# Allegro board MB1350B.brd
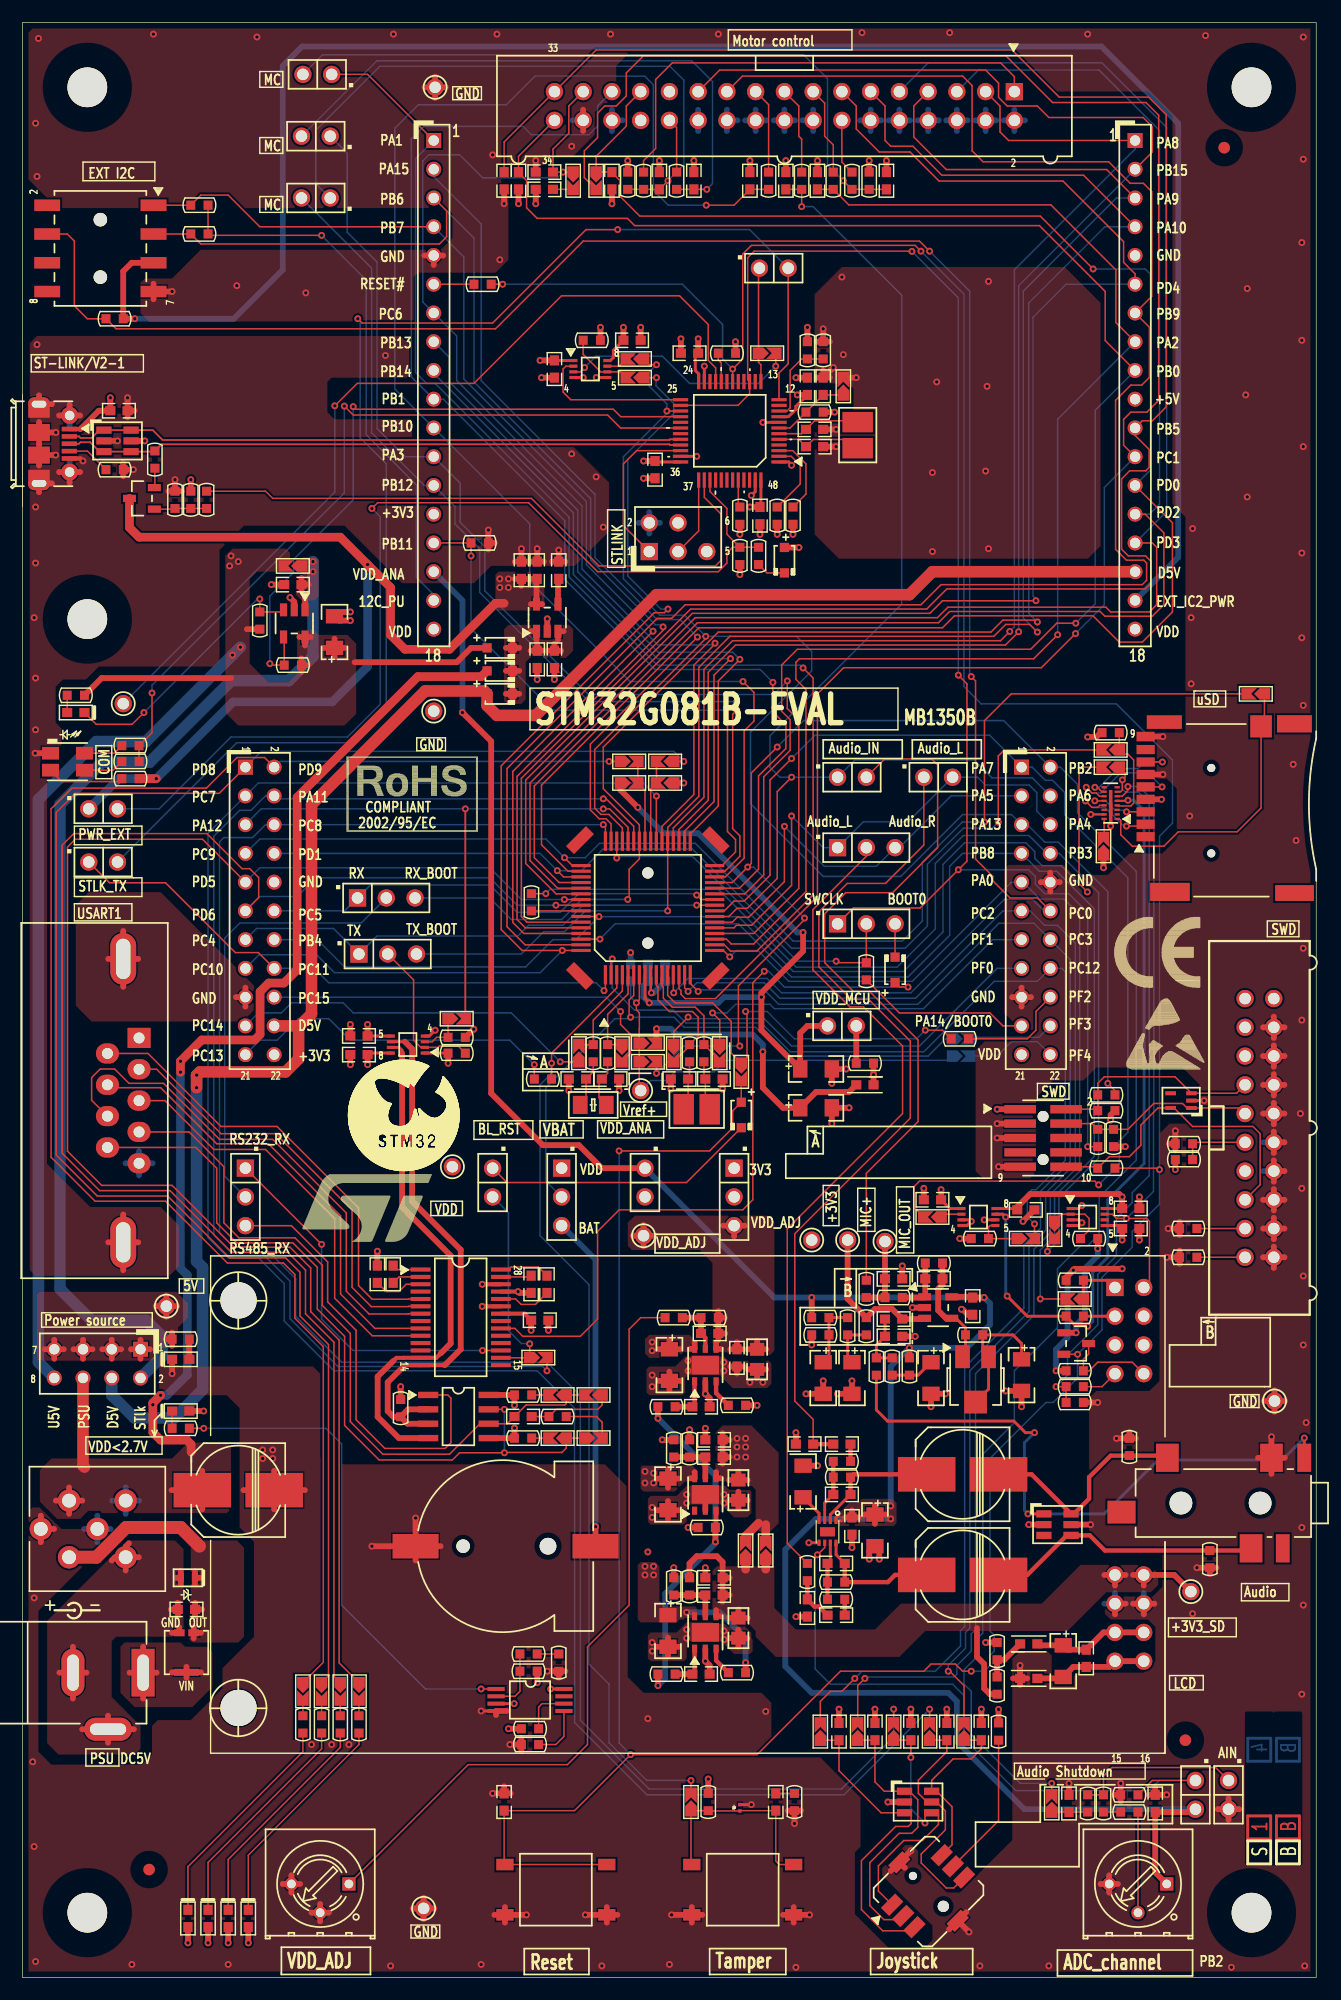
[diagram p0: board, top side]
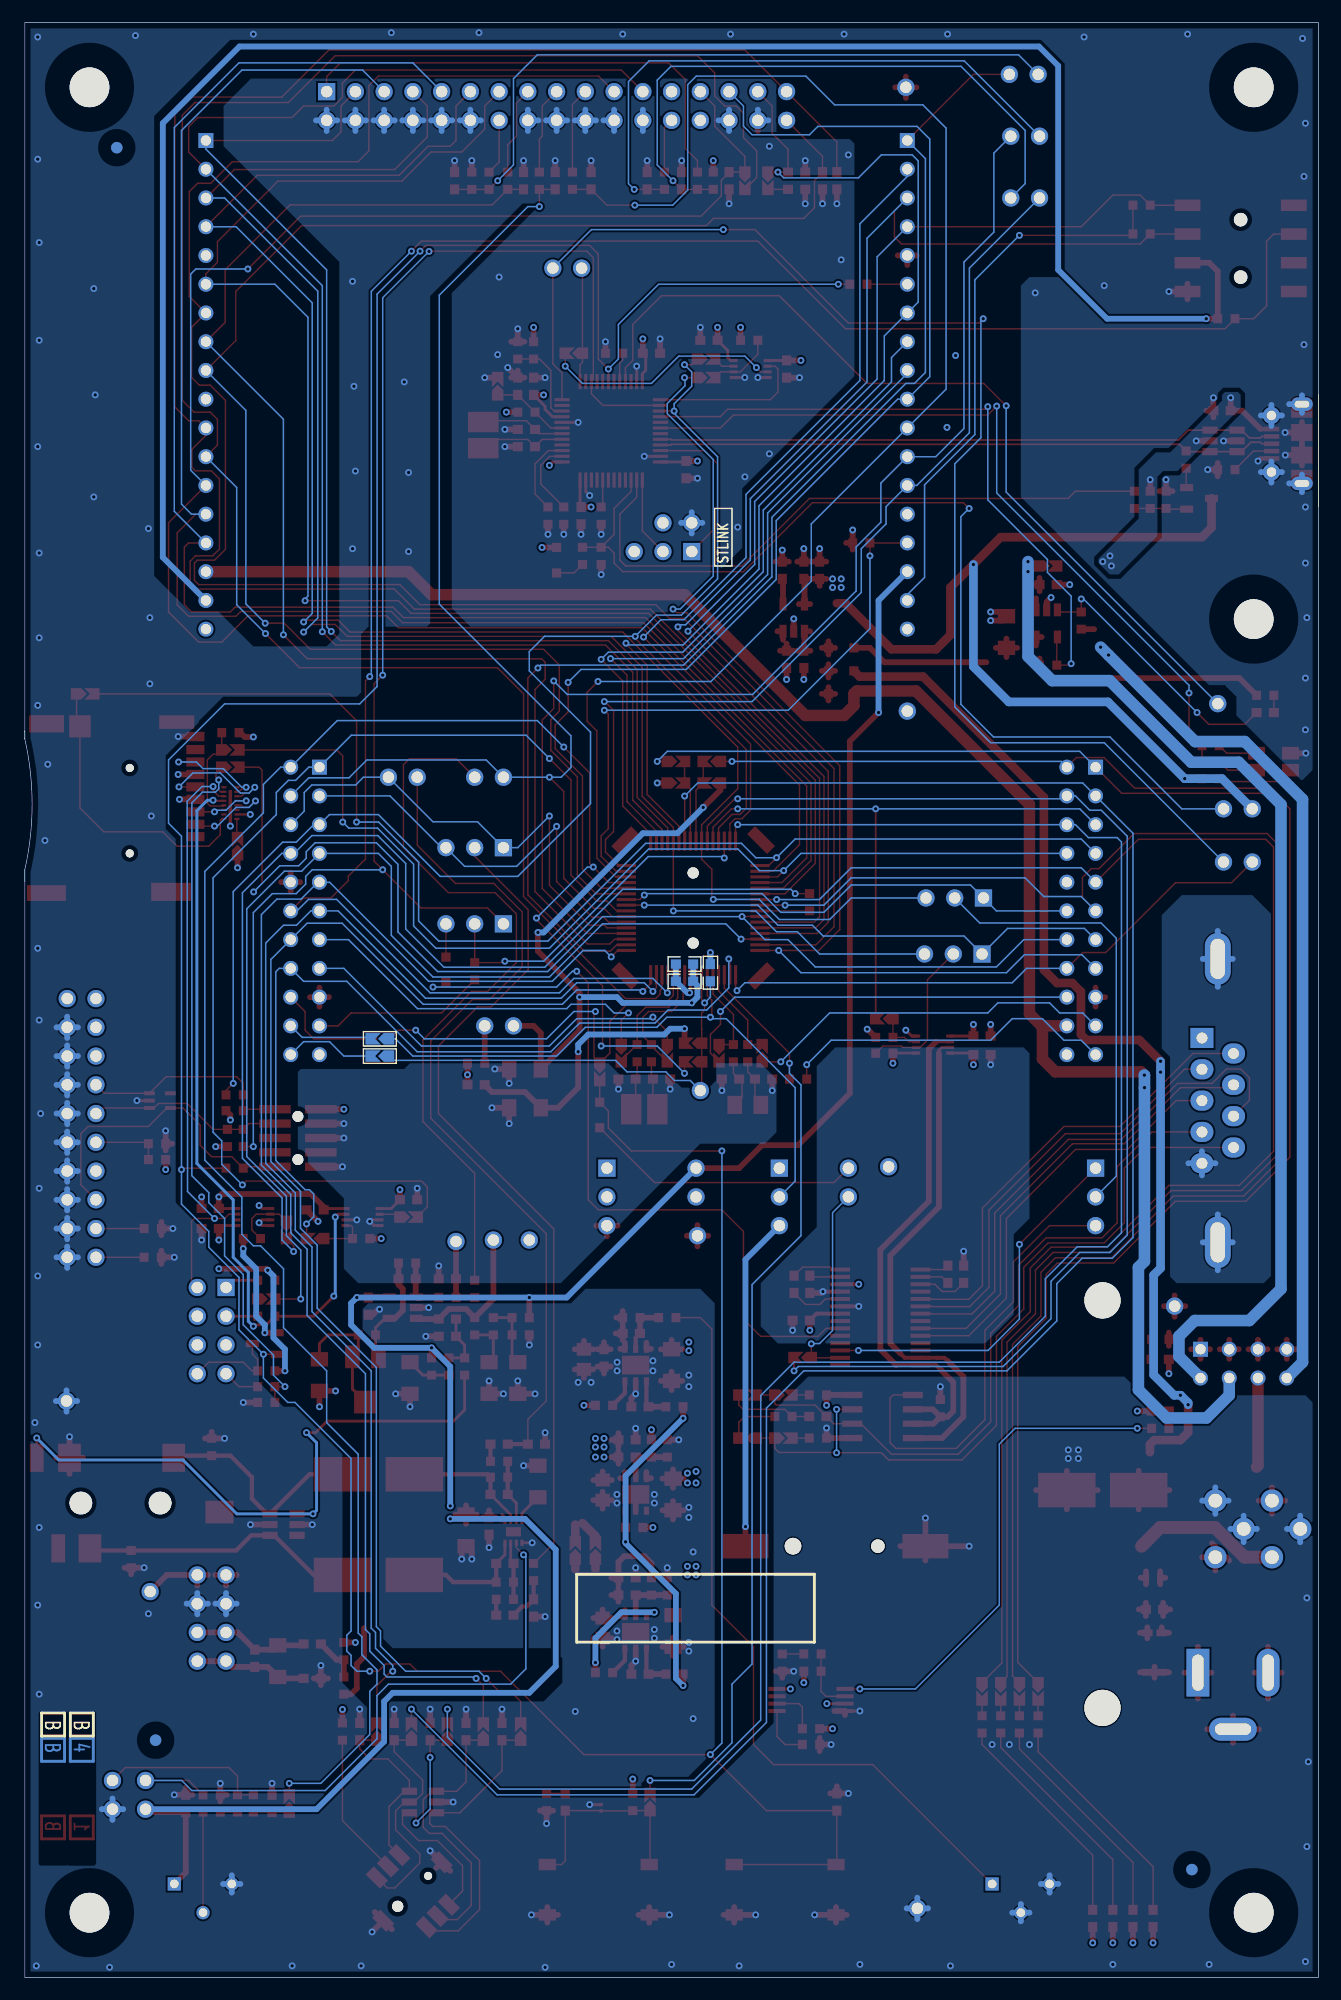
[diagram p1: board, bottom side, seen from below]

Outline 114.3 x 172.72 mm; copper layers: TOP, L2_VCC, L3_GND, BOTTOM. Coordinates in mm from the lower left corner of the outline.
Outline path: 114.3,110.11 114.3,172.72 0,172.72 0,0 114.3,0 114.3,96.86 ; 114.3,110.11 114.3,109.43 ; 114.3,110.11 114.3,109.43 ; 114.3,109.43 arc(113.66,103.65) 114.3,97.87 ; 114.3,97.87 114.3,96.86 ; 114.3,97.87 114.3,96.86

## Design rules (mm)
net group STL_USB_D: nets STL_USB_DM STL_USB_DP

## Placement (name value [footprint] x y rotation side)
B1  TD-0341 [RESET_Black]  [PB10]  47.12 7.75 0 top
B2  Tamper  [PB10]  63.63 7.75 0 top
B3  -  [MT-008A]  80.01 7.62 315 top
BT1  CR1220 holder  [BAT_2SM_CR1220]  42.67 38.1 180 top
C1  [N_A]  [0603C]  46.1 159.51 0 top
C2  [N_A]  [0603C]  42.55 158.75 90 top
C3  [N_A]  [0603C]  43.81 158.75 90 top
C4  [N_A]  [0603C]  52.07 158.75 90 top
C5  1nF  [0603C]  56.26 158.75 270 top
C6  100nF  [0603C]  59.31 158.75 270 top
C7  [N_A]  [0603C]  64.26 158.75 270 top
C8  [N_A]  [0603C]  67.44 158.75 270 top
C9  [N_A]  [0603C]  70.23 158.75 270 top
C10  100nF  [0603C]  76.33 158.75 270 top
C11  10nF  [0603C]  46.1 157.99 0 top
C12  100nF  [0603C]  53.85 144.65 180 top
C13  100nF  [0603C]  58.93 143.51 0 top
C14  100nF  [0603C]  46.99 142.11 90 top
C15  100nF  [0603C]  69.34 140.59 270 top
C16  100nF  [0603C]  70.74 140.59 270 top
C17  100nF  [0603C]  8.51 138.43 180 top
C18  10pF  [0603C]  69.98 136.78 0 top
C19  10pF  [0603C]  69.98 135.25 0 top
C20  100nF  [0603C]  55.88 133.22 90 top
C21  100nF  [0603C]  65.15 129.16 90 top
C22  100nF  [0603C]  44.07 124.33 270 top
C23  1uF_X5R_0603  [0603C]  45.47 124.33 90 top
C24  10nF_X7R_0603  [0603C]  47.37 124.33 270 top
C25  100nF  [0603C]  23.88 123.06 0 top
C26  1uF_X5R_0603  [0603C]  45.47 116.46 90 top
C27  100nF  [0603C]  46.99 116.46 90 top
C28  4.7uF  [TAN-A]  27.56 118.87 270 top
C29  100nF  [0603C]  29.72 83.19 0 top
C30  100nF  [0603C]  29.72 81.53 0 top
C31  4.7uF  [TAN-A]  70.1 80.26 180 top
C32  100nF  [0603C]  56.01 89.53 180 bottom
C33  100nF  [0603C]  56.01 88.01 0 bottom
C34  3.9pF  [0603C]  49.02 79.38 180 top
C35  3.9pF  [0603C]  51.94 79.38 0 top
C36  3.9pF  [0603C]  58.04 79.38 180 top
C37  3.9pF  [0603C]  61.09 79.38 0 top
C38  10nF  [0603C]  53.72 88.77 270 bottom
C39  1uF  [TAN-A]  70.1 76.83 180 top
C40  100nF  [0603C]  80.39 68.71 0 top
C41  100nF  [0603C]  97.92 67.94 180 top
C42  100nF  [0603C]  88.65 67.82 180 top
C43  100nF  [0603C]  97.92 66.17 180 top
C44  100nF  [0603C]  31.34 62.13 90 top
C45  100nF  [0603C]  32.74 62.13 270 top
C46  [N_A]  [0603C]  76.96 61.72 0 top
C47  180pF  [0603C]  80.52 61.72 180 top
C48  100nF  [0603C]  44.93 61.24 270 top
C49  100nF  [0603C]  46.33 61.24 90 top
C50  100nF  [0603C]  83.95 59.31 90 top
C51  100nF  [0603C]  76.96 58.17 0 top
C52  100nF  [0603C]  45.69 58.06 180 top
C53  [N_A]  [0603C]  60.71 56.9 0 top
C54  47pF  [0603C]  76.96 56.64 0 top
C55  100nF  [0603C]  63.12 54.74 270 top
C56  10uF[ESR<0.2ohm]  [0805C]  64.9 54.61 270 top
C57  4.7uF  [TAN-A]  57.15 54.1 90 top
C58  4.7uF  [TAN-A]  88.27 53.21 90 top
C59  4.7uF  [TAN-A]  70.74 52.96 90 top
C60  2.2uF  [TAN-A]  73.28 52.96 90 top
C61  10uF  [TAN-A]  80.26 52.96 90 top
C62  [N_A]  [0603C]  59.94 50.42 0 top
C63  100nF  [0603C]  44.22 49.56 180 top
C64  100nF  [0603C]  61.09 47.5 180 top
C65  [N_A]  [0603C]  69.09 47.12 0 top
C66  330nF  [0603C]  72.39 47.12 0 top
C67  [N_A]  [0603C]  61.09 45.97 0 top
C68  220uF  [C310M-6]  83.06 44.45 180 top
C69  1uF  [TAN-A]  68.96 43.81 270 top
C70  220uF  [C310M-6]  19.05 43.05 180 top
C71  10uF[ESR<0.2ohm]  [0805C]  63.25 43.05 270 top
C72  4.7uF  [TAN-A]  57.02 42.67 90 top
C73  1.5nF  [0603C]  72.39 42.67 0 top
C74  100nF  [0603C]  73.28 39.88 90 top
C75  1uF  [TAN-A]  75.31 39.5 90 top
C76  1.5nF  [0603C]  71.88 36.58 0 top
C77  220uF  [C310M-6]  83.06 35.56 180 top
C78  [N_A]  [0603C]  69.34 32.64 90 top
C79  100nF  [0603C]  14.48 32.51 180 top
C80  330nF  [0603C]  71.88 32 0 top
C81  100nF  [0603C]  93.98 28.19 270 top
C82  10uF  [TAN-A]  91.95 27.94 90 top
C83  100nF  [0603C]  72.14 21.72 270 top
C84  100nF  [0603C]  75.31 21.72 270 top
C85  100nF  [0603C]  78.49 21.72 270 top
C86  100nF  [0603C]  81.66 21.72 270 top
C87  100nF  [0603C]  84.71 21.72 270 top
C88  100nF  [0603C]  42.55 15.49 270 top
C89  100nF  [0603C]  66.55 15.49 270 top
C90  [N_A]  [0603C]  92.46 15.37 270 top
C91  100nF  [0603C]  100.08 15.37 270 top
C92  4.7uF  [TAN-A]  57.02 30.61 90 top
C93  [N_A]  [0603C]  59.94 26.8 0 top
C94  [N_A]  [0603C]  61.09 33.78 0 top
C95  10uF[ESR<0.2ohm]  [0805C]  63.25 30.86 270 top
C96  100nF  [0603C]  61.09 35.31 180 top
CN1  MC_connector  [IDC34S]  87.63 166.62 270 top
CN2  F206A-2_04MGF-A  [SSM-104-L-DH]  6.87 152.77 90 top
CN3  [N_A]  [SIP2]  65.1 151.03 0 top
CN4  Header 18X1  [HDR_1X18_2R54]  36.32 162.31 270 top
CN5  Header 18X1  [HDR_1X18_2R54]  98.3 162.31 270 top
CN6  1050170001  [MICRO_USB_B_105017]  4.05 135.51 270 top
CN7  [N_A]  [HDR_2X3-1_2R54-6]  55.37 125.98 0 top
CN8  PJS008-2000 (SMS064FF or SMS128FF)  [MSD_PJS008_]  105.03 99.31 90 top
CN9  Header 11X2  [HDR_2X11_2R54]  19.68 106.93 270 top
CN10  Header 11X2  [HDR_2X11_2R54]  88.27 106.93 270 top
CN11  DB9-male USART1  [DB9_M]  10.29 77.47 90 top
CN12  SWD  [IDC20S]  108.01 86.49 0 top
CN13  -  [FTSH-105-01-L-DV]  90.17 74.17 270 top
CN14  2.4" LCD connector (MB895C)  [MB895CS]  96.52 60.96 0 top
CN15  PJ3028B-3  [PJ3028B]  109.35 41.91 180 top
CN16  DC-10B  [PWR_JACK_DC10]  10.64 26.92 0 top
CN17  -  [SIP2]  106.55 17.4 270 top
D1  BAT60JFILM  [SOD-323]  67.31 125.22 270 top
D2  BAT60JFILM  [SOD-323]  42.16 117.47 0 top
D3  BAT60JFILM  [SOD-323]  42.16 113.41 0 top
D4  BAT60JFILM  [SOD-323]  77.09 89.03 90 top
D5  BAT60JFILM  [SOD-323]  63.5 76.2 270 top
D6  ESDA6V1BC6  [SOT23-6L]  91.44 40.01 270 top
D7  ESDA7P60-1U1M  [DO_2SM_1R6X1_21]  14.61 35.31 180 top
D8  ESDA6V1-5SC6  [SOT23-6L]  79.12 15.49 270 top
D9  ESDALC6V1-1U2  [D0201_21]  63.37 14.99 90 top
D10  BAT60JFILM  [SOD-323]  42.16 115.44 0 top
JP1  -  [SIP2]  27.3 168.15 180 top
JP2  -  [SIP2]  27.18 162.69 180 top
JP3  -  [SIP2]  27.18 157.23 180 top
JP4  -  [SIP2]  72.01 106.05 0 top
JP5  -  [SIP2]  5.84 103.25 0 top
JP6  -  [SIP3]  72.01 99.82 0 top
JP7  -  [SIP2]  5.84 98.55 0 top
JP8  -  [SIP3]  29.59 95.38 0 top
JP9  -  [SIP3]  72.01 93.09 0 top
JP10  -  [SIP3]  29.72 90.42 0 top
JP11  -  [SIP2]  71.12 84.07 0 top
JP12  -  [SIP2]  41.53 71.5 270 top
JP13  -  [SIP2]  54.99 71.5 270 top
JP14  -  [SIP3]  19.68 71.5 270 top
JP15  -  [SIP3]  47.62 71.5 270 top
JP16  -  [SIP3]  62.87 71.5 270 top
JP17  Header 4X2  [HDR_2X4_2R54]  10.41 55.5 180 top
JP18  -  [SIP2]  103.63 17.4 270 top
JP19  -  [SIP2]  79.63 106.05 0 top
L1  BEAD(FCM1608KF-601T03)  [0603L]  74.42 78.87 180 top
L2  BNX002-01  [BNX001]  6.6 39.62 180 top
L3  BEAD  [0603L]  88.9 29.46 0 top
L4  BEAD  [0603L]  88.9 26.42 0 top
LD1  Green  [0603D]  19.94 5.21 90 top
LD2  Orange  [0603D]  18.16 5.21 90 top
LD3  Red  [0603D]  16.38 5.21 90 top
LD4  Blue  [0603D]  14.61 5.21 90 top
LD5  Red  [0603D]  4.7 111.76 0 top
LD6  HSMF-A201-A00J1  [LED2_3528]  3.96 107.42 270 top
LD7  red  [0603D]  13.97 54.61 180 top
LD8  Orange  [0603D]  13.97 50.04 180 top
NOREF  -  [unnamed]  106.17 161.67 0 top
NOREF#2  -  [#2]  0 0 0 top
NOREF#3  -  [#2]  -1.14 -10.67 0 top
NOREF#4  -  [unnamed]  5.71 120.02 0 top
NOREF#5  -  [#2]  395.73 -43.74 0 top
NOREF#6  -  [#2]  233.48 163.12 0 top
NOREF#7  -  [unnamed]  5.71 5.71 0 top
NOREF#8  -  [unnamed]  102.74 20.95 0 top
NOREF#9  -  [#2]  112.57 13.25 90 top
NOREF#10  -  [#2]  6.35 209.55 0 top
NOREF#11  -  [unnamed]  108.58 5.71 0 top
NOREF#12  -  [#2]  110.03 13.25 90 top
NOREF#13  -  [unnamed]  108.58 167 0 top
NOREF#14  -  [unnamed]  11.18 9.53 0 top
NOREF#15  -  [#2]  170.18 202.69 0 top
NOREF#16  -  [unnamed]  5.71 167 0 top
NOREF#17  -  [unnamed]  11.18 9.53 180 bottom
NOREF#18  -  [unnamed]  106.17 161.67 180 bottom
NOREF#19  -  [unnamed]  102.74 20.95 180 bottom
R1  3.3K  [0603R]  53.47 158.75 90 top
R2  0  [0603R]  54.86 158.75 270 top
R3  0  [0603R]  57.78 158.75 270 top
R4  0  [0603R]  65.91 158.75 90 top
R5  0  [0603R]  68.83 158.75 90 top
R6  0  [0603R]  71.63 158.75 90 top
R7  0  [0603R]  73.28 158.75 270 top
R8  100K  [0603R]  74.8 158.75 270 top
R9  10K  [0603R]  15.62 156.59 0 top
R10  10K  [0603R]  15.62 154.05 0 top
R11  820  [0603R]  40.64 149.61 180 top
R12  10K  [0603R]  8.13 146.56 0 top
R13  100K  [0603R]  50.29 144.65 0 top
R14  4.7K  [0603R]  69.34 143.76 270 top
R15  4.7K  [0603R]  70.74 143.76 270 top
R16  100K  [0603R]  62.23 143.51 180 top
R17  100K  [0603R]  69.98 138.3 0 top
R18  1.5K  [0603R]  11.68 134.11 270 top
R19  100K  [0603R]  8.13 133.22 0 top
R20  36K  [0603R]  13.46 130.56 270 top
R21  10K  [0603R]  14.86 130.56 90 top
R22  100  [0603R]  16.26 130.56 90 top
R23  100K  [0603R]  63.37 129.16 90 top
R24  10K  [0603R]  66.67 129.16 90 top
R25  [N_A]  [0603R]  68.07 129.16 90 top
R26  10K  [0603R]  40.39 126.75 180 top
R27  4.7K  [0603R]  63.37 125.6 270 top
R28  2.7K  [0603R]  65.02 125.6 90 top
R31  100K  [0603R]  20.95 119.89 90 top
R32  10K  [0603R]  23.88 115.95 180 top
R33  1K  [0603R]  4.7 113.28 180 top
R34  10K  [0603R]  96.14 109.98 180 top
R35  100  [0603R]  9.53 108.84 180 top
R36  100  [0603R]  9.53 107.44 180 top
R37  0  [0603R]  9.53 105.92 0 top
R38  0  [0603R]  44.96 95 90 top
R39  10K  [0603R]  74.55 88.9 90 top
R40  100K  [0603R]  38.35 83.06 0 top
R41  820  [0603R]  82.8 82.93 0 top
R42  100K  [0603R]  38.35 81.66 180 top
R43  0  [0603R]  50.42 81.66 90 top
R44  0  [0603R]  51.69 81.66 90 top
R45  0  [0603R]  58.93 81.66 90 top
R46  0  [0603R]  60.2 81.66 90 top
R47  820  [0603R]  45.97 79.38 0 top
R48  22  [0603R]  95.76 77.98 0 top
R49  [N_A]  [0603R]  95.76 76.58 0 top
R50  22  [0603R]  95 74.17 270 top
R51  [N_A]  [0603R]  96.39 74.17 90 top
R52  10K  [0603R]  102.62 73.66 0 top
R53  [N_A]  [0603R]  102.62 72.26 180 top
R54  22  [0603R]  95.76 71.5 0 top
R55  10K  [0603R]  103 66.17 0 top
R56  10K  [0603R]  84.58 65.28 180 top
R57  100K  [0603R]  94.23 65.28 0 top
R58  10K  [0603R]  103 63.63 0 top
R59  82K  [0603R]  80.52 63.12 0 top
R60  10K  [0603R]  92.96 61.59 180 top
R61  510  [0603R]  74.55 60.83 270 top
R62  0  [0603R]  76.96 60.07 0 top
R63  270  [0603R]  92.96 58.42 180 top
R64  11.8K[1%]  [0603R]  57.53 58.29 180 top
R65  22.1K[1%]  [0603R]  60.71 58.29 180 top
R66  100K  [0603R]  70.48 58.29 0 top
R67  15K  [0603R]  72.9 57.53 270 top
R68  18K  [0603R]  74.55 57.53 90 top
R69  100K  [0603R]  70.48 56.77 180 top
R70  680  [0603R]  84.07 56.77 0 top
R71  1K  [0603R]  13.97 56.39 180 top
R72  100  [0603R]  75.44 53.98 270 top
R73  2.2K  [0603R]  76.83 53.98 270 top
R74  1K  [0603R]  78.36 53.98 90 top
R75  4.7K  [0603R]  92.96 53.59 180 top
R76  270  [0603R]  92.96 52.2 0 top
R77  22K  [0603R]  44.22 51.46 180 top
R78  10K  [0603R]  92.96 50.8 180 top
R79  [N_A]  [0603R]  63.12 50.55 180 top
R80  [N_A]  [0603R]  56.9 50.42 180 top
R81  10K  [0603R]  33.4 50.29 270 top
R82  120  [0603R]  47.27 49.56 0 top
R83  510  [0603R]  13.97 48.51 0 top
R84  0  [0603R]  74.42 80.77 0 top
R85  22K  [0603R]  44.22 47.65 180 top
R86  1K  [0603R]  97.79 46.86 270 top
R87  11.8K[1%]  [0603R]  57.53 46.74 90 top
R88  20.5K[1%]  [0603R]  58.93 46.74 270 top
R89  20K  [0603R]  72.39 45.59 180 top
R90  4.7K  [0603R]  72.39 44.2 0 top
R91  [N_A]  [0603R]  60.45 39.75 180 top
R92  1K  [0603R]  104.9 36.96 90 top
R93  0  [0603R]  69.34 35.81 270 top
R94  4.7K  [0603R]  71.88 34.92 0 top
R95  20K  [0603R]  71.88 33.4 180 top
R96  0  [0603R]  86.11 28.83 270 top
R97  4.53K[1%]  [0603R]  44.7 28.57 180 top
R98  0  [0603R]  47.37 27.81 270 top
R99  1K[1%]  [0603R]  44.7 27.05 0 top
R100  [N_A]  [0603R]  86.11 25.78 90 top
R101  680  [0603R]  24.77 22.35 270 top
R102  680  [0603R]  26.42 22.35 270 top
R103  680  [0603R]  28.07 22.35 270 top
R104  510  [0603R]  29.72 22.35 270 top
R105  0  [0603R]  44.83 21.97 0 top
R106  100  [0603R]  86.23 21.72 270 top
R107  0  [0603R]  44.83 20.57 0 top
R108  10K  [0603R]  97.79 16.13 180 top
R109  4.7K  [0603R]  60.58 15.49 90 top
R110  100  [0603R]  68.2 15.49 90 top
R111  0  [0603R]  94.11 15.37 90 top
R112  47  [0603R]  95.5 15.37 270 top
R113  0  [0603R]  97.79 14.61 0 top
R114  [N_A]  [0603R]  63.12 26.92 0 top
R115  0  [0603R]  56.9 26.8 180 top
R116  20.5K[1%]  [0603R]  58.93 34.54 270 top
R117  11.8K[1%]  [0603R]  57.53 34.54 90 top
RV1  [N_A]  [PTF_3314J]  84.2 52.83 180 top
RV2  3386P-503H[5%]  [3386P]  26.29 8.26 180 top
RV3  10K  [3386P]  98.55 8.26 180 top
SB1  Solder Bridge OFF  [SB_0603]  48.64 158.75 90 top
SB2  Solder Bridge OFF  [SB_0603]  50.67 158.75 90 top
SB3  Solder Bridge ON  [SB_0603]  65.79 143.51 180 top
SB4  Solder Bridge ON  [SB_0603]  54.1 143 0 top
SB5  Solder Bridge ON  [SB_0603]  54.1 141.35 0 top
SB6  Solder Bridge OFF  [SB_0603]  72.52 140.59 270 top
SB7  Solder Bridge OFF  [SB_0603]  23.88 124.71 0 top
SB8  Solder Bridge ON  [SB_0603]  108.97 113.41 0 top
SB9  Solder Bridge ON  [SB_0603]  96.14 108.46 0 top
SB10  Solder Bridge ON  [SB_0603]  53.59 107.44 180 top
SB11  Solder Bridge ON  [SB_0603]  56.77 107.44 0 top
SB12  Solder Bridge ON  [SB_0603]  96.14 106.93 0 top
SB13  Solder Bridge OFF  [SB_0603]  53.59 105.54 180 top
SB14  Solder Bridge OFF  [SB_0603]  56.77 105.54 0 top
SB15  Solder Bridge OFF  [SB_0603]  95.5 99.95 270 top
SB16  Solder Bridge ON  [SB_0603]  38.35 84.71 180 top
SB17  Solder Bridge OFF  [SB_0603]  55.24 80.9 180 top
SB18  Solder Bridge OFF  [SB_0603]  49.15 81.66 270 top
SB19  Solder Bridge OFF  [SB_0603]  52.96 81.66 90 top
SB20  Solder Bridge OFF  [SB_0603]  57.53 81.66 90 top
SB21  Solder Bridge OFF  [SB_0603]  61.59 81.66 90 top
SB22  Solder Bridge ON  [SB_0603]  55.24 82.55 180 top
SB23  Solder Bridge ON  [SB_0603]  63.5 80.01 90 top
SB24  Solder Bridge ON  [SB_0603]  80.39 67.18 0 top
SB25  Solder Bridge ON  [SB_0603]  91.19 66.04 90 top
SB26  Solder Bridge ON  [SB_0603]  88.65 65.28 180 top
SB27  Solder Bridge ON  [SB_0603]  92.96 59.94 0 top
SB28  Solder Bridge ON  [SB_0603]  45.57 54.76 180 top
SB29  Solder Bridge OFF  [SB_0603]  47.27 51.46 0 top
SB30  Solder Bridge OFF  [SB_0603]  50.44 51.46 0 top
SB31  Solder Bridge OFF  [SB_0603]  47.27 47.65 0 top
SB32  Solder Bridge OFF  [SB_0603]  50.44 47.65 180 top
SB33  Solder Bridge ON  [SB_0603]  24.77 25.27 90 top
SB34  Solder Bridge ON  [SB_0603]  26.42 25.27 90 top
SB35  Solder Bridge ON  [SB_0603]  28.07 25.27 90 top
SB36  Solder Bridge ON  [SB_0603]  29.72 25.27 90 top
SB37  Solder Bridge ON  [SB_0603]  70.48 21.72 270 top
SB38  Solder Bridge ON  [SB_0603]  73.79 21.72 270 top
SB39  Solder Bridge ON  [SB_0603]  76.96 21.72 270 top
SB40  Solder Bridge ON  [SB_0603]  80.14 21.72 270 top
SB41  Solder Bridge ON  [SB_0603]  83.19 21.72 270 top
SB42  Solder Bridge ON  [SB_0603]  59.05 15.49 270 top
SB43  Solder Bridge ON  [SB_0603]  90.93 15.37 270 top
SB44  Solder Bridge OFF  [SB_0603]  82.93 82.93 180 bottom
SB45  Solder Bridge OFF  [SB_0603]  82.93 81.41 180 bottom
SB46  Solder Bridge OFF  [SB_0603]  65.66 37.72 270 top
SB47  Solder Bridge OFF  [SB_0603]  63.88 37.72 270 top
T1  9013  [SOT-23]  10.54 130.68 0 top
T2  BSN20  [SOT-23]  93.09 56.01 180 top
TP1  Ground  [TP]  36.45 167 270 top
TP2  PB10  [TP]  8.89 112.55 0 top
TP3  Ground  [TP]  36.32 111.89 270 top
TP4  VREF+  [TP]  54.61 78.36 180 top
TP5  VDD  [TP]  37.97 71.63 90 top
TP6  VDD_ADJ  [TP]  54.86 65.53 90 top
TP7  +3V3  [TP]  69.72 65.15 90 top
TP8  MIC+  [TP]  72.9 65.15 0 top
TP9  MIC_OUT  [TP]  76.2 65.02 0 top
TP10  5V  [TP]  12.7 59.31 0 top
TP11  Ground  [TP]  110.62 50.93 270 top
TP12  Ground  [TP]  35.43 6.1 0 top
TP13  +3V3_SD  [TP]  103.23 34.09 0 top
U1  SN74LVC2T45DCUT  [USOP8_0R5_2X3R1]  50.16 142.11 270 top
U2  STM32F103CBT6  [LQFP48_0R5_9X9]  62.48 136.65 180 top
U3  USBLC6-2SC6  [SOT23-6L]  8.38 135.76 270 top
U4  LDK120M33R  [SOT23-5]  46.35 120.14 0 top
U5  STMPS2141STR  [SOT23-5]  24 119.63 180 top
U6  EMIF06-MSD02N16  [DFN16_0R4_3R5X1R2]  96.14 103.76 90 top
U7  STM32G0  [QFP64_0R5_12X12_SKT]  55.24 94.49 90 top
U8  SN74LVC2T45DCUT  [USOP8_0R5_2X3R1]  34.04 82.42 90 top
U9  ESDALC6V1W5  [SC70-5]  102.36 77.47 90 top
U10  SN74LVC2T45DCUT  [USOP8_0R5_2X3R1]  84.45 67.18 270 top
U11  SN74LVC2T45DCUT  [USOP8_0R5_2X3R1]  94.11 67.18 270 top
U12  TS461CLT  [SOT23-5]  80.9 59.18 270 top
U13  ST3241EBPR  [SSOP28_0R65_10R2X7R8]  38.71 58.32 270 top
U14  ST1L05BPUR  [DFN6_0R95_3X3]  60.33 54.1 0 top
U15  ST3485EBDR  [SOIC8_1R27_4R9X6]  38.51 49.56 270 top
U16  ST1L05BPUR  [DFN6_0R95_3X3]  60.33 42.67 0 top
U17  TS488IQT  [DFN8_0R5_2X2]  71.12 39.37 180 top
U18  ZEN056V130A24LS  [TYCO_ZEN056V130A24LS]  14.48 28.7 90 top
U19  TS3702IPT  [TSSOP8_0R65_3X6R4]  44.83 24.51 270 top
U21  ST1L05BPUR  [DFN6_0R95_3X3]  60.33 30.48 0 top
X1  NX3225GD-8.000M-EXS00A-CG04874  [XTAL_2SM_3R2X2R5_H1]  73.79 136.27 270 top
X2  NX3215SA-32.768KHZ-EXS00A-MU00525  [XTAL_2SM_3R2X1R5]  50.42 77.09 180 top
X3  NX3225GD-8.000M-EXS00A-CG04874  [XTAL_2SM_3R2X2R5_H1]  59.56 76.71 180 top

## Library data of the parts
B1 B2 = PB10
B3 = MT-008A
BT1 = BAT_2SM_CR1220
C1-C27 C29 C30 C32-C38 C40-C55 C62-C67 C73 C74 C76 C78-C81 C83-C91 C93 C94 C96 = 0603C
C28 C31 C39 C57-C61 C69 C72 C75 C82 C92 = TAN-A
C56 C71 C95 = 0805C
C68 C70 C77 = C310M-6
CN1 = IDC34S
CN2 = SSM-104-L-DH
CN3 CN17 JP1-JP5 JP7 JP11-JP13 JP18 JP19 = SIP2
CN4 CN5 = HDR_1X18_2R54
CN6 = MICRO_USB_B_105017
CN7 = HDR_2X3-1_2R54-6
CN8 = MSD_PJS008_
CN9 CN10 = HDR_2X11_2R54
CN11 = DB9_M
CN12 = IDC20S
CN13 = FTSH-105-01-L-DV
CN14 = MB895CS
CN15 = PJ3028B
CN16 = PWR_JACK_DC10
D1-D5 D10 = SOD-323
D6 D8 U3 = SOT23-6L
D7 = DO_2SM_1R6X1_21
D9 = D0201_21
JP6 JP8-JP10 JP14-JP16 = SIP3
JP17 = HDR_2X4_2R54
L1 L3 L4 = 0603L
L2 = BNX001
LD1-LD5 LD7 LD8 = 0603D
LD6 = LED2_3528
R1-R28 R31-R117 = 0603R
RV1 = PTF_3314J
RV2 RV3 = 3386P
SB1-SB47 = SB_0603
T1 T2 = SOT-23
TP1-TP13 = TP
U1 U8 U10 U11 = USOP8_0R5_2X3R1
U2 = LQFP48_0R5_9X9
U4 U5 U12 = SOT23-5
U6 = DFN16_0R4_3R5X1R2
U7 = QFP64_0R5_12X12_SKT
U9 = SC70-5
U13 = SSOP28_0R65_10R2X7R8
U14 U16 U21 = DFN6_0R95_3X3
U15 = SOIC8_1R27_4R9X6
U17 = DFN8_0R5_2X2
U18 = TYCO_ZEN056V130A24LS
U19 = TSSOP8_0R65_3X6R4
X1 X3 = XTAL_2SM_3R2X2R5_H1
X2 = XTAL_2SM_3R2X1R5

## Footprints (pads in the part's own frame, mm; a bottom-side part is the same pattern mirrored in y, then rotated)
0603C
  rect 0.889x0.813 smd: 1(-0.762,0) 2(0.762,0)
0603D
  rect 0.889x0.813 smd: 1(-0.762,0) 2(0.762,0)
0603L
  rect 0.889x0.813 smd: 1(-0.762,0) 2(0.762,0)
0603R
  rect 0.787x0.813 smd: 1(-0.762,0) 2(0.762,0)
0805C
  rect 1.143x1.27 smd: 1(-0.889,0) 2(0.889,0)
3386P
  rect 1.168x1.168 hole 0.762: 1(-2.54,0)
  round 1.168 hole 0.762: 2(0,2.54) 3(2.54,0)
BAT_2SM_CR1220
  round 1.473 hole 1.473 unplated: (-3.75,0)
  round 1.194 hole 1.194 unplated: (3.75,0)
  rect 4.064x2.159 smd: 1(-7.95,0) 2(7.95,0)
BNX001
  round 1.981 hole 1.219: 1(2.5,2.5) 2(-2.5,2.5) 3(2.5,-2.5) 4(0,0) 5(5,0) 6(-2.5,-2.5)
C310M-6
  rect 5.08x3.048 smd: 1(3.175,0) 2(-3.175,0)
D0201_21
  rect 0.305x0.305 smd: 1(-0.28,0) 2(0.28,0)
DB9_M
  rect 1.778x2.032 hole 0.965: 1(5.537,0)
  oval 1.778x2.032 hole 0.965: 2(2.769,0) 3(0,0) 4(-2.769,0) 5(-5.537,0) 6(4.166,2.794) 7(1.397,2.794) 8(-1.372,2.794) 9(-4.14,2.794)
  oval 4.572x2.286 hole 3.556x1.27: 10(-12.522,1.397) 11(12.522,1.397)
DFN6_0R95_3X3
  rect 0.457x0.711 smd: 1(-0.95,-1.436) 2(0,-1.436) 3(0.95,-1.436) 4(0.95,1.436) 5(0,1.436) 6(-0.95,1.436)
  rect 2.413x1.651 smd: 7(0,0)
DFN8_0R5_2X2
  rect 0.279x0.559 smd: 1(-0.75,-0.97) 2(-0.25,-0.97) 3(0.25,-0.97) 4(0.75,-0.97) 5(0.75,0.97) 6(0.25,0.97) 7(-0.25,0.97) 8(-0.75,0.97)
  rect 1.321x0.813 smd: 9(0,0)
DFN16_0R4_3R5X1R2
  rect 0.203x0.457 smd: 1(-1.4,-0.575) 2(-1,-0.575) 3(-0.6,-0.575) 4(-0.2,-0.575) 5(0.2,-0.575) 6(0.6,-0.575) 7(1,-0.575) 8(1.4,-0.575) 9(1.4,0.575) 10(1,0.575) 11(0.6,0.575) 12(0.2,0.575) 13(-0.2,0.575) 14(-0.6,0.575) 15(-1,0.575) 16(-1.4,0.575)
  rect 2.311x0.305 smd: 17(0,0)
DO_2SM_1R6X1_21
  rect 0.559x0.787 smd: 1(-0.625,0) 2(0.625,0)
FTSH-105-01-L-DV
  round 0.965 hole 0.965 unplated: (-1.905,0) (1.905,0)
  rect 0.737x2.794 smd: 1(-2.54,-2.03) 2(-2.54,2.03) 3(-1.27,-2.03) 4(-1.27,2.03) 5(0,-2.03) 6(0,2.03) 7(1.27,-2.03) 8(1.27,2.03) 9(2.54,-2.03) 10(2.54,2.03)
HDR_1X18_2R54
  rect 1.321x1.321 hole 0.914: 1(0,0)
  round 1.321 hole 0.914: 2(2.54,0) 3(5.08,0) 4(7.62,0) 5(10.16,0) 6(12.7,0) 7(15.24,0) 8(17.78,0) 9(20.32,0) 10(22.86,0) 11(25.4,0) 12(27.94,0) 13(30.48,0) 14(33.02,0) 15(35.56,0) 16(38.1,0) 17(40.64,0) 18(43.18,0)
HDR_2X3-1_2R54-6
  rect 1.524x1.524 hole 1.016: 1(0,0)
  round 1.524 hole 1.016: 2(0,2.54) 3(2.54,0) 4(2.54,2.54) 5(5.08,0)
HDR_2X4_2R54
  rect 1.321x1.321 hole 0.914: 1(0,0)
  round 1.321 hole 0.914: 2(0,2.54) 3(2.54,0) 4(2.54,2.54) 5(5.08,0) 6(5.08,2.54) 7(7.62,0) 8(7.62,2.54)
HDR_2X11_2R54
  rect 1.321x1.321 hole 0.914: 1(0,0)
  round 1.321 hole 0.914: 2(0,2.54) 3(2.54,0) 4(2.54,2.54) 5(5.08,0) 6(5.08,2.54) 7(7.62,0) 8(7.62,2.54) 9(10.16,0) 10(10.16,2.54) 11(12.7,0) 12(12.7,2.54) 13(15.24,0) 14(15.24,2.54) 15(17.78,0) 16(17.78,2.54) 17(20.32,0) 18(20.32,2.54) 19(22.86,0) 20(22.86,2.54) 21(25.4,0) 22(25.4,2.54)
IDC20S
  round 1.524 hole 1.016: 1(0,0) 2(2.54,0) 3(0,-2.54) 4(2.54,-2.54) 5(0,-5.08) 6(2.54,-5.08) 7(0,-7.62) 8(2.54,-7.62) 9(0,-10.16) 10(2.54,-10.16) 11(0,-12.7) 12(2.54,-12.7) 13(0,-15.24) 14(2.54,-15.24) 15(0,-17.78) 16(2.54,-17.78) 17(0,-20.32) 18(2.54,-20.32) 19(0,-22.86) 20(2.54,-22.86)
IDC34S
  rect 1.524x1.524 hole 1.016: 1(0,0)
  round 1.524 hole 1.016: 2(2.54,0) 3(0,-2.54) 4(2.54,-2.54) 5(0,-5.08) 6(2.54,-5.08) 7(0,-7.62) 8(2.54,-7.62) 9(0,-10.16) 10(2.54,-10.16) 11(0,-12.7) 12(2.54,-12.7) 13(0,-15.24) 14(2.54,-15.24) 15(0,-17.78) 16(2.54,-17.78) 17(0,-20.32) 18(2.54,-20.32) 19(0,-22.86) 20(2.54,-22.86) 21(0,-25.4) 22(2.54,-25.4) 23(0,-27.94) 24(2.54,-27.94) 25(0,-30.48) 26(2.54,-30.48) 27(0,-33.02) 28(2.54,-33.02) 29(0,-35.56) 30(2.54,-35.56) 31(0,-38.1) 32(2.54,-38.1) 33(0,-40.64) 34(2.54,-40.64)
LED2_3528
  rect 1.118x1.499 smd: 1(-0.75,-1.5) 2(-0.75,1.5) 3(0.75,1.5) 4(0.75,-1.5)
LQFP48_0R5_9X9
  rect 1.346x0.279 smd: 1(-4.35,2.75) 2(-4.35,2.25) 3(-4.35,1.75) 4(-4.35,1.25) 5(-4.35,0.75) 6(-4.35,0.25) 7(-4.35,-0.25) 8(-4.35,-0.75) 9(-4.35,-1.25) 10(-4.35,-1.75) 11(-4.35,-2.25) 12(-4.35,-2.75) 25(4.35,-2.75) 26(4.35,-2.25) 27(4.35,-1.75) 28(4.35,-1.25) 29(4.35,-0.75) 30(4.35,-0.25) 31(4.35,0.25) 32(4.35,0.75) 33(4.35,1.25) 34(4.35,1.75) 35(4.35,2.25) 36(4.35,2.75)
  rect 0.279x1.346 smd: 13(-2.75,-4.35) 14(-2.25,-4.35) 15(-1.75,-4.35) 16(-1.25,-4.35) 17(-0.75,-4.35) 18(-0.25,-4.35) 19(0.25,-4.35) 20(0.75,-4.35) 21(1.25,-4.35) 22(1.75,-4.35) 23(2.25,-4.35) 24(2.75,-4.35) 37(2.75,4.35) 38(2.25,4.35) 39(1.75,4.35) 40(1.25,4.35) 41(0.75,4.35) 42(0.25,4.35) 43(-0.25,4.35) 44(-0.75,4.35) 45(-1.25,4.35) 46(-1.75,4.35) 47(-2.25,4.35) 48(-2.75,4.35)
MB895CS
  round 3.2 hole 3.2 unplated: (-77.443,-1.143) (-77.443,-37.153)
  rect 1.524x1.524 hole 1.016: 1(0,0)
  round 1.524 hole 1.016: 2(2.54,0) 3(0,-2.54) 4(2.54,-2.54) 5(0,-5.08) 6(2.54,-5.08) 7(0,-7.62) 8(2.54,-7.62) 9(0,-25.4) 10(2.54,-25.4) 11(0,-27.94) 12(2.54,-27.94) 13(0,-30.48) 14(2.54,-30.48) 15(0,-33.02) 16(2.54,-33.02)
MICRO_USB_B_105017
  rect 0.406x1.346 smd: 1(-1.3,0.075) 2(-0.65,0.075) 3(0,0.075) 4(0.65,0.075) 5(1.3,0.075)
  oval 1.194x1.905 hole 0.61x1.295: 6(-3.5,-2.6) 7(3.5,-2.6)
  round 1.499 hole 0.838: 8(-2.5,0.1) 9(2.5,0.1)
  rect 1.499x1.905 smd: 10(-1,-2.6) 11(1,-2.6)
MSD_PJS008_
  round 0.711 hole 0.711 unplated: (0,0) (7.55,0)
  rect 0.813x1.6 smd: 1(1.475,5.8) 2(2.575,5.8) 3(3.675,5.8) 4(4.775,5.8) 5(5.875,5.8) 6(6.975,5.8) 7(8.075,5.8) 8(9.175,5.8)
  rect 0.838x1.6 smd: 9(10.325,5.8)
  rect 1.956x1.905 smd: 10(11.225,-4.4)
  rect 1.524x3.073 smd: 11(11.45,-7.35)
  rect 1.397x3.429 smd: 12(-3.503,-7.357)
  rect 1.6x3.505 smd: 13(-3.4,3.65)
  rect 1.194x3.099 smd: 14(11.6,4.15)
MT-008A
  round 0.711 hole 0.711 unplated: (-1.9,0)
  round 0.991 hole 0.991 unplated: (1.9,0)
  rect 1.016x1.778 smd: 1(-1.4,-3.1) 2(0,-3.1) 3(1.4,-3.1) 4(1.4,3.1) 5(0,3.1) 6(-1.4,3.1) 7(-3.6,0) 8(3.7,0)
PB10
  rect 1.524x1.016 smd: 1(-4.5,-2.223) 2(-4.5,2.223) 3(4.5,2.223) 4(4.5,-2.223)
PJ3028B
  round 2.007 hole 2.007 unplated: (0,0) (7,0)
  rect 1.219x2.489 smd: 2(-3.9,-4) 7(-2,4)
  rect 2.007x2.489 smd: 3(-1,-4) 4(0.8,4) 6(8.2,-4)
  rect 2.489x2.007 smd: 5(12.25,0.8)
PTF_3314J
  rect 1.295x2.007 smd: 1(1.15,-2) 3(-1.15,-2)
  rect 2.007x2.007 smd: 2(0,2)
PWR_JACK_DC10
  rect 2.032x4.216 hole 1.016x3.2: 1(0,0)
  oval 4.216x2.032 hole 3.2x1.016: 2(-3.1,-5)
  oval 2.032x4.216 hole 1.016x3.2: 3(-6.2,0)
QFP64_0R5_12X12_SKT
  round 0.991 hole 0.991 unplated: (-3.1,0) (3.1,0)
  rect 1.702x0.279 smd: 1(-5.9,3.75) 2(-5.9,3.25) 3(-5.9,2.75) 4(-5.9,2.25) 5(-5.9,1.75) 6(-5.9,1.25) 7(-5.9,0.75) 8(-5.9,0.25) 9(-5.9,-0.25) 10(-5.9,-0.75) 11(-5.9,-1.25) 12(-5.9,-1.75) 13(-5.9,-2.25) 14(-5.9,-2.75) 15(-5.9,-3.25) 16(-5.9,-3.75) 33(5.9,-3.75) 34(5.9,-3.25) 35(5.9,-2.75) 36(5.9,-2.25) 37(5.9,-1.75) 38(5.9,-1.25) 39(5.9,-0.75) 40(5.9,-0.25) 41(5.9,0.25) 42(5.9,0.75) 43(5.9,1.25) 44(5.9,1.75) 45(5.9,2.25) 46(5.9,2.75) 47(5.9,3.25) 48(5.9,3.75)
  rect 0.279x1.702 smd: 17(-3.75,-5.9) 18(-3.25,-5.9) 19(-2.75,-5.9) 20(-2.25,-5.9) 21(-1.75,-5.9) 22(-1.25,-5.9) 23(-0.75,-5.9) 24(-0.25,-5.9) 25(0.25,-5.9) 26(0.75,-5.9) 27(1.25,-5.9) 28(1.75,-5.9) 29(2.25,-5.9) 30(2.75,-5.9) 31(3.25,-5.9) 32(3.75,-5.9) 49(3.75,5.9) 50(3.25,5.9) 51(2.75,5.9) 52(2.25,5.9) 53(1.75,5.9) 54(1.25,5.9) 55(0.75,5.9) 56(0.25,5.9) 57(-0.25,5.9) 58(-0.75,5.9) 59(-1.25,5.9) 60(-1.75,5.9) 61(-2.25,5.9) 62(-2.75,5.9) 63(-3.25,5.9) 64(-3.75,5.9)
  rect 2.489x0.991 smd rot 45: 65(-6,6) 67(6,-6)
  rect 2.489x0.991 smd rot 135: 66(6,6) 68(-6,-6)
SB_0603
  round 0.152 smd: 1(-0.762,0) 2(0.762,0)
SC70-5
  rect 0.356x0.94 smd: 1(-0.65,-0.92) 2(0,-0.92) 3(0.65,-0.92) 4(0.65,0.92) 5(-0.65,0.92)
SIP2
  round 1.524 hole 1.016: 1(0,0) 2(2.54,0)
SIP3
  rect 1.524x1.524 hole 1.016: 1(0,0)
  round 1.524 hole 1.016: 2(2.54,0) 3(5.08,0)
SOD-323
  rect 0.813x0.813 smd: 1(-1.125,0) 2(1.125,0)
SOIC8_1R27_4R9X6
  rect 0.559x1.778 smd: 1(-1.905,-2.675) 2(-0.635,-2.675) 3(0.635,-2.675) 4(1.905,-2.675) 5(1.905,2.675) 6(0.635,2.675) 7(-0.635,2.675) 8(-1.905,2.675)
SOT23-5
  rect 0.635x1.143 smd: 1(-0.95,-1.2) 2(0,-1.2) 3(0.95,-1.2) 4(0.95,1.2) 5(-0.95,1.2)
SOT23-6L
  rect 0.635x1.346 smd: 1(-0.95,-1.2) 2(0,-1.2) 3(0.95,-1.2) 4(0.95,1.2) 5(0,1.2) 6(-0.95,1.2)
SOT-23
  rect 1.143x0.635 smd: 1(1.1,-0.95) 2(1.1,0.95) 3(-1.1,0)
SSM-104-L-DH
  round 1.194 hole 1.194 unplated: (-2.54,0) (2.54,0)
  rect 1.016x2.286 smd: 1(3.81,-4.698) 2(3.81,4.698) 3(1.27,-4.698) 4(1.27,4.698) 5(-1.27,-4.698) 6(-1.27,4.698) 7(-3.81,-4.698) 8(-3.81,4.698)
SSOP28_0R65_10R2X7R8
  rect 0.356x1.753 smd: 1(-4.225,-3.55) 2(-3.575,-3.55) 3(-2.925,-3.55) 4(-2.275,-3.55) 5(-1.625,-3.55) 6(-0.975,-3.55) 7(-0.325,-3.55) 8(0.325,-3.55) 9(0.975,-3.55) 10(1.625,-3.55) 11(2.275,-3.55) 12(2.925,-3.55) 13(3.575,-3.55) 14(4.225,-3.55) 15(4.225,3.55) 16(3.575,3.55) 17(2.925,3.55) 18(2.275,3.55) 19(1.625,3.55) 20(0.975,3.55) 21(0.325,3.55) 22(-0.325,3.55) 23(-0.975,3.55) 24(-1.625,3.55) 25(-2.275,3.55) 26(-2.925,3.55) 27(-3.575,3.55) 28(-4.225,3.55)
TAN-A
  rect 1.27x1.524 smd: 1(1.397,0) 2(-1.397,0)
TP
  round 1.524 hole 1.016: 1(0,0)
TSSOP8_0R65_3X6R4
  rect 0.356x1.524 smd: 1(-0.975,-3) 2(-0.325,-3) 3(0.325,-3) 4(0.975,-3) 5(0.975,3) 6(0.325,3) 7(-0.325,3) 8(-0.975,3)
TYCO_ZEN056V130A24LS
  rect 0.61x2.21 smd: 1(-1.745,0)
  rect 0.61x0.94 smd: 2(1.745,0.635) 3(1.745,-0.635)
unnamed
  round 1.016 smd: (0,0)
USOP8_0R5_2X3R1
  rect 0.279x0.711 smd: 1(-0.75,-1.5) 2(-0.25,-1.5) 3(0.25,-1.5) 4(0.75,-1.5) 5(0.75,1.5) 6(0.25,1.5) 7(-0.25,1.5) 8(-0.75,1.5)
XTAL_2SM_3R2X1R5
  rect 1.295x1.6 smd: 1(-1.15,0) 2(1.15,0)
XTAL_2SM_3R2X2R5_H1
  rect 1.803x2.692 smd: 1(-1.15,0) 2(1.15,0)

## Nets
+3V3: C14.2 C30.2 C52.2 C64.1 C67.2 C71.1 CN1.28 CN4.14 CN9.22 JP16.1 LD1.1 LD2.1 LD3.1 LD4.1 LD8.1 R1.2 R77.2 R88.1 R99.2 SB46.1 SB47.1 TP7.1 U1.1 U8.8 U13.22 U13.26 U15.8 U16.4 U19.8
+3V3_PG: R80.2 R91.1 R115.2 U16.3
+3V3_SD: C41.2 C42.2 C94.2 C95.1 C96.1 CN8.4 CN14.9 CN14.10 R34.2 R60.2 R75.2 R100.1 R116.1 SB15.2 SB46.2 SB47.2 TP13.1 U6.15 U10.8 U11.8 U21.4
+3V3_SD_PG: R114.1 U21.3
+3V3_ST_LINK: C13.2 C15.2 C20.2 C21.2 C22.2 C23.1 CN7.4 JP5.1 R17.2 R37.2 T1.3 U2.1 U2.9 U2.24 U2.36 U2.48 U4.5
+5V: C57.1 C72.1 C92.1 CN1.25 CN5.10 D1.1 JP17.1 JP17.3 JP17.5 JP17.7 R71.2 R79.1 R91.2 R96.1 R114.2 TP10.1 U14.6 U16.6 U21.6
D5V: CN5.16 CN9.20 D3.1 JP17.4
GND: B1.1 B1.4 B2.1 B2.4 B3.7 B3.8 BT1.2 C1.1 C2.1 C3.1 C4.1 C5.1 C6.1 C7.1 C8.1 C9.1 C10.1 C11.1 C12.1 C13.1 C14.1 C15.1 C16.1 C17.1 C18.2 C19.2 C20.1 C21.1 C22.1 C23.2 C24.1 C25.1 C26.1 C27.1 C28.2 C29.1 C30.1 C31.2 C32.1 C33.2 C34.2 C35.2 C36.2 C37.2 C38.1 C39.2 C40.1 C41.1 C42.1 C43.1 C44.2 C46.2 C48.2 C50.1 C52.1 C54.2 C55.2 C56.2 C57.2 C58.2 C59.2 C60.2 C61.2 C62.2 C64.2 C65.1 C69.2 C70.2 C71.2 C72.2 C74.1 C75.2 C78.1 C83.1 C84.1 C85.1 C86.1 C87.1 C88.1 C90.1 C91.1 C92.2 C93.2 C95.2 C96.2 CN1.2 CN1.4 CN1.6 CN1.8 CN1.10 CN1.12 CN1.16 CN1.18 CN1.20 CN1.22 CN1.24 CN1.30 CN1.32 CN2.7 CN4.5 CN5.5 CN6.5 CN6.6 CN6.7 CN6.8 CN6.9 CN6.10 CN6.11 CN7.2 CN8.6 CN8.9 CN9.10 CN9.17 CN10.10 CN10.17 CN11.5 CN11.10 CN11.11 CN12.4 CN12.6 CN12.8 CN12.10 CN12.12 CN12.14 CN12.16 CN12.18 CN12.20 CN13.3 CN13.5 CN13.9 CN14.11 CN14.12 CN15.3 CN17.2 D6.2 D6.5 D8.2 D9.2 L2.4 L2.5 L2.6 L4.1 LD6.1 LD7.2 R8.1 R15.1 R16.1 R19.2 R20.1 R23.1 R24.1 R25.1 R26.1 R27.2 R51.1 R52.1 R55.1 R58.1 R69.2 R78.1 R81.1 R85.2 R86.1 R87.2 R92.1 R98.2 R107.1 R108.2 R110.1 R117.2 RV2.2 RV2.3 RV3.3 SB6.1 SB14.2 TP1.1 TP3.1 TP11.1 TP12.1 U1.4 U1.5 U2.8 U2.23 U2.35 U2.47 U3.2 U4.2 U5.2 U6.17 U7.9 U8.4 U9.2 U10.3 U10.4 U10.6 U11.3 U11.4 U12.2 U13.23 U13.25 U14.2 U14.7 U15.5 U16.2 U16.7 U17.5 U19.4 U21.2 U21.7
VDD: C12.2 C29.2 C40.2 C43.2 CN4.18 CN5.18 CN10.21 CN12.1 CN12.2 CN13.1 JP13.2 JP15.1 JP16.2 L1.1 R13.2 R14.1 R40.2 R42.2 R49.2 R53.2 R56.2 R57.2 R84.2 R105.1 R106.1 R109.2 T2.1 TP5.1 U1.8 U8.1 U8.5 U10.1 U11.1 U11.5 U19.3
VDD_ADJ: C53.2 C55.1 C56.1 JP16.3 R65.1 TP6.1 U14.4
VDD_ANA: C50.2 C74.2 C75.1 C91.2 CN4.16 JP13.1 JP18.2 R66.1 R74.2 RV3.1 U12.5 U17.1
VDD_MCU: C31.1 C32.2 C33.1 JP11.1 SB13.2 U7.8
VDD_PG: R79.2 U14.3
AIN_1: R14.2 R15.2 U2.10
BOOTLOADER_BOOT0: D4.1 U13.20
BOOTLOADER_RESET: JP12.2 SB28.2 U13.16
E5V: C70.1 D10.1 JP17.6 L2.3
EXT_I2C_PWR: CN2.5 CN5.17 R12.2
I2C_PU: CN4.17 R9.2 R10.2
LED_STLINK: R35.1 R36.1 U2.30
MCO: U2.29
NETB2_2: B2.2 B2.3 C89.2 D9.1 R109.1 SB42.2
NETB3_1: B3.1 C85.2 D8.4 SB39.2
NETB3_2: B3.2 C84.2 D8.1 SB38.2
NETB3_3: B3.3 C83.2 D8.3 SB37.2
NETB3_4: B3.4 C86.2 D8.5 SB40.2
NETB3_5: B3.5 R106.2
NETB3_6: B3.6 C87.2 D8.6 SB41.2
NETBT1_1: BT1.1 JP15.3
NETC5_2: C5.2 JP3.1 R1.1 R2.2
NETC6_2: C6.2 JP2.2 R3.2
NETC10_2: C10.2 JP1.2 R7.2 R8.2
NETC11_2: C11.2 SB1.1
NETC24_2: C24.2 U4.4
NETC26_2: C26.2 C27.2 D2.2 D3.2 D10.2 U4.1 U4.3
NETC34_1: C34.1 R43.1 X2.2
NETC35_1: C35.1 R44.1 X2.1
NETC36_1: C36.1 R45.1 X3.2
NETC37_1: C37.1 R46.1 X3.1
NETC44_1: C44.1 U13.3
NETC45_1: C45.1 U13.1
NETC45_2: C45.2 U13.2
NETC46_1: C46.1 R61.2 R62.1 TP9.1
NETC47_1: C47.1 R59.2 R70.1 RV1.1 U12.4
NETC47_2: C47.2 R59.1 R62.2 U12.1
NETC48_1: C48.1 U13.27
NETC49_1: C49.1 U13.24
NETC49_2: C49.2 U13.28
NETC51_1: C51.1 C54.1 R72.1 R73.1
NETC51_2: C51.2 R68.2 TP8.1 U12.3
NETC53_1: C53.1 R64.1 R65.2 U14.5
NETC58_1: C58.1 R70.2 RV1.2 RV1.3
NETC59_1: C59.1 R66.2 R67.1 R69.1
NETC60_1: C60.1 R67.2 R68.1
NETC61_1: C61.1 R73.2 R74.1
NETC62_1: C62.1 R80.1 U14.1
NETC63_1: C63.1 R82.1 SB30.2
NETC63_2: C63.2 CN11.4 SB29.2 SB30.1 U15.6
NETC65_2: C65.2 C66.1 JP19.1
NETC66_2: C66.2 R89.1
NETC67_1: C67.1 R87.1 R88.2 U16.5
NETC68_1: C68.1 C73.2 R90.2 U17.2
NETC68_2: C68.2 CN15.6 D6.6 R86.2
NETC69_1: C69.1 U17.4
NETC73_1: C73.1 R89.2 R90.1 U17.3
NETC76_1: C76.1 R94.1 R95.2 U17.7
NETC76_2: C76.2 C77.1 R94.2 U17.8
NETC77_2: C77.2 CN15.4 D6.4 R92.2
NETC78_2: C78.2 C80.1 R93.2
NETC79_1: C79.1 D7.1 L2.1 U18.3
NETC79_2: C79.2 CN16.2 CN16.3 D7.2 L2.2 U18.2
NETC80_2: C80.2 R95.1
NETC81_1: C81.1 C82.1 CN14.13 CN14.14 L3.2
NETC81_2: C81.2 C82.2 CN14.15 CN14.16 L4.2
NETC89_1: C89.1 R110.2
NETC90_2: C90.2 R111.1 SB43.2
NETC93_1: C93.1 R115.1 U21.1
NETC94_1: C94.1 R116.2 R117.1 U21.5
NETCN1_1: CN1.1 R2.1
NETCN1_14: CN1.14 R7.1
NETCN1_15: CN1.15 R6.2
NETCN1_17: CN1.17 R5.2
NETCN1_19: CN1.19 R4.2
NETCN1_26: CN1.26 R3.1
NETCN4_6: CN4.6 R11.2
NETCN6_4: CN6.4 R19.1
NETCN8_2: CN8.2 U6.13
NETCN8_3: CN8.3 U6.12
NETCN8_5: CN8.5 U6.11
NETCN8_7: CN8.7 U6.10
NETCN8_10: CN8.10 SB8.2 U6.1
NETCN9_18: CN9.18 SB19.1
NETCN9_19: CN9.19 SB18.2
NETCN9_21: CN9.21 R47.1
NETCN10_13: CN10.13 SB21.2
NETCN10_15: CN10.15 SB20.2
NETCN10_18: CN10.18 R41.2
NETCN10_19: CN10.19 R39.1
NETCN10_20: CN10.20 SB44.1
NETCN10_22: CN10.22 SB45.1
NETCN11_2: CN11.2 U13.6
NETCN11_3: CN11.3 U13.10
NETCN11_6: CN11.6 U13.5
NETCN11_7: CN11.7 U13.9
NETCN11_8: CN11.8 U13.7
NETCN11_9: CN11.9 SB31.2 SB32.2 U15.7
NETCN12_7: CN12.7 CN13.2 R48.1 R49.1 U9.3
NETCN12_9: CN12.9 CN13.4 R50.1 R51.2 U9.1
NETCN12_11: CN12.11 R52.2 R53.1
NETCN12_15: CN12.15 CN13.10 R54.1 U9.5
NETCN12_17: CN12.17 R55.2
NETCN12_19: CN12.19 R58.2
NETCN14_1: CN14.1 R60.1 SB27.2
NETCN14_3: CN14.3 R63.1
NETCN14_7: CN14.7 R76.2
NETCN14_8: CN14.8 R75.1 T2.3
NETCN15_2: CN15.2 D6.1 R72.2
NETCN16_1: CN16.1 U18.1
NETCN17_1: CN17.1 R111.2 R112.1
NETD1_2: D1.2 R28.1
NETD4_2: D4.2 JP9.3
NETD5_2: D5.2 JP12.1
NETJP4_2: JP4.2 R61.1
NETJP5_2: JP5.2 R27.1 R28.2 U2.39
NETJP6_2: JP6.2 R93.1
NETJP8_2: JP8.2 JP14.2
NETJP10_2: JP10.2 R42.1 U8.2
NETJP11_2: JP11.2 R84.1
NETJP14_1: JP14.1 U13.17
NETJP14_3: JP14.3 U15.1
NETJP18_1: JP18.1 R108.1 U17.6
NETL3_1: L3.1 R96.2 R100.2
NETLD1_2: LD1.2 R104.2
NETLD2_2: LD2.2 R103.2
NETLD3_2: LD3.2 R102.2
NETLD4_2: LD4.2 R101.2
NETLD5_1: LD5.1 R33.2
NETLD5_2: LD5.2 R31.2 U5.3
NETLD6_2: LD6.2 R35.2
NETLD6_3: LD6.3 R36.2
NETLD6_4: LD6.4 R37.1
NETLD7_1: LD7.1 R71.1
NETLD8_2: LD8.2 R83.1
NETR13_1: R13.1 SB5.1 U1.6
NETR16_2: R16.2 U2.20
NETR18_2: R18.2 T1.2
NETR20_2: R20.2 R21.1 R22.1 T1.1
NETR23_2: R23.2 U2.44
NETR24_2: R24.2 U2.2
NETR25_2: R25.2 U2.3
NETR34_1: R34.1 SB9.2 U6.4
NETR38_1: R38.1 U7.57
NETR40_1: R40.1 SB16.2 U8.3
NETR56_1: R56.1 SB26.2 U10.5
NETR57_1: R57.1 SB25.2 U11.2
NETR64_2: R64.2 RV2.1
NETR76_1: R76.1 R78.2 SB12.2 U6.7
NETR77_1: R77.1 SB29.1
NETR82_2: R82.2 SB32.1
NETR83_2: R83.2 U19.1
NETR85_1: R85.1 SB31.1
NETR97_1: R97.1 R98.1
NETR97_2: R97.2 R99.1 U19.2
NETR101_1: R101.1 SB33.1
NETR102_1: R102.1 SB34.1
NETR103_1: R103.1 SB35.1
NETR104_1: R104.1 SB36.1
NETR105_2: R105.2 U19.6
NETR107_2: R107.2 U19.5
NETR112_2: R112.2 R113.1
NETR113_2: R113.2 RV3.2
NETSB4_1: SB4.1 U1.7
NETSB10_1: SB10.1 SB13.1 U7.41
NETSB11_1: SB11.1 SB14.1 U7.40
NETSB15_1: SB15.1 U6.16
NETSB24_2: SB24.2 U10.2
NETTP2_1: TP2.1 U2.21
OSC_IN: C19.1 U2.5 X1.2
OSC_OUT: C18.1 U2.6 X1.1
PA0: CN10.9 SB38.1 U7.17
PA1: CN4.1 JP1.1 U7.18
PA2: C9.2 CN5.8 R6.1 U7.19
PA3: CN4.12 JP2.1 U7.20
PA4: CN10.6 JP6.1 JP19.2 U7.21
PA5: CN10.3 JP6.3 U7.22
PA6: C8.2 CN10.4 JP4.1 R5.1 U7.23
PA7: CN10.1 SB24.1 U7.24
PA8: CN1.3 CN5.1 U7.36
PA9: CN1.7 CN5.3 JP10.3 U7.37
PA10: CN1.11 CN5.4 JP8.3 U7.42
PA11: CN9.4 SB28.1 U7.43
PA12: CN9.5 SB16.1 U7.44
PA13: CN10.5 R48.2 SB4.2 U2.27 U7.45
PA14: JP9.2 R39.2 U7.46
PA15: CN4.2 U7.47
PB0: C3.2 CN1.34 CN5.9 U7.27
PB1: CN1.29 CN4.10 U7.28
PB2: CN10.2 SB17.1 SB43.1 U7.29
PB3: CN10.8 R38.2 SB25.1
PB4: CN9.14 SB12.1 U7.58
PB5: C2.2 CN1.33 CN5.11 U7.59
PB6: CN2.3 CN4.3 R10.1 U7.60
PB7: CN2.1 CN4.4 R9.1 U7.61
PB8: CN10.7 SB27.1 U7.62
PB9: CN1.21 CN5.7 U7.63
PB10: C7.2 CN4.11 R4.1 U7.30
PB11: CN4.15 R26.2 U7.31
PB12: CN4.13 JP3.2 U7.32
PB13: CN4.8 U7.33
PB14: CN4.9 U7.34
PB15: CN1.23 CN5.2 U7.35
PC0: CN2.4 CN10.12 R12.1 U7.13
PC1: CN5.12 SB2.1 U7.14
PC2: CN10.11 SB41.1 U7.15
PC3: CN10.14 SB37.1 U7.16
PC4: CN9.13 JP10.1 U7.25
PC5: CN9.12 JP8.1 U7.26
PC6: C1.2 CN1.31 CN4.7 SB1.2 U7.38
PC7: CN9.3 SB40.1 U7.39
PC8: CN9.6 SB39.1 U7.48
PC9: CN9.7 SB8.1 U7.49
PC10: CN9.15 SB5.2 U7.64
PC11: CN9.16 JP7.1 U7.1
PC12: CN10.16 SB26.1 U7.2
PC13: R47.2 SB42.1 U7.3
PC14: R43.2 SB18.1 U7.4
PC15: R44.2 SB19.2 U7.5
PD0: C4.2 CN1.27 CN5.13 SB2.2 U7.50
PD1: CN9.8 SB9.1 U7.51
PD2: CN1.5 CN5.14 U7.52
PD3: CN1.9 CN5.15 U7.53
PD4: CN1.13 CN5.6 U7.54
PD5: CN9.9 SB36.2 U7.55
PD6: CN9.11 SB35.2 U7.56
PD8: CN9.1 SB11.2 SB34.2
PD9: CN9.2 SB10.2 SB33.2
PF0: R45.2 SB20.1 U7.10
PF1: R46.2 SB21.1 U7.11
PF2: R41.1 SB23.2 U7.12
PF3: JP15.2 SB44.2 U7.6
PF4: C38.2 SB17.2 SB22.2 SB45.2 TP4.1 U7.7
PWR_ENN: R32.2 U2.28 U5.4
RESET#: B1.2 B1.3 C88.2 D5.1 R11.1 R54.2 SB23.1 T2.2 U2.18
SPI1_MOSI_3V3: R63.2 U6.5 U10.7
SPI1_SCK_3V3: CN14.2 U6.6 U11.7
STL_USB_DM: CN6.2 U2.32 U3.1 U3.6
STL_USB_DP: CN6.3 R18.1 U2.33 U3.3 U3.4
STLINK_RX: CN3.1 SB3.2 U2.13
STLINK_TX: CN3.2 JP7.2 U2.12
STLK_RX: SB3.1 U1.3
STM_JTCK_SWCLK: CN7.3 U2.37
STM_JTMS_SWDIO: CN7.1 U2.34
STM_RST: C16.2 R17.1 SB6.2 U2.7
SWIM_PU_CTRL: U2.4
T_JRST: U2.19
T_JTCK: JP9.1 R50.2 U2.15 U2.26
T_JTDI: U2.17
T_JTDO: U2.16
T_SWDIO_IN: U1.2 U2.25
T_SWO: U2.31
U5V_ST_LINK: C25.2 JP17.2 SB7.2 U5.1
USART1_RTS_3V3: R81.2 U8.6 U13.14 U15.2 U15.3
USART1_TX_3V3: U8.7 U13.13 U15.4
USB_RENUMN: R22.2 U2.38
VREF+: C39.1 L1.2 SB22.1
VUSB_ST_LINK: C17.2 C28.1 CN6.1 D2.1 JP17.8 R21.2 R31.1 R32.1 R33.1 SB7.1 U3.5 U5.5

Pads without a net: CN2 2 6 8; CN7 5; CN8 1 8 11 12 13 14; CN11 1; CN12 3 5 13; CN13 6 7 8; CN14 4 5 6; CN15 5 7; D6 3; U2 11 14 22 40 41 42 43 45 46; U6 2 3 8 9 14; U7 65 66 67 68; U9 4; U11 6; U13 4 8 11 12 15 18 19 21; U16 1; U17 9; U19 7

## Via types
v1: diameter 0.61, hole 0.305, TOP to BOTTOM, 522 vias

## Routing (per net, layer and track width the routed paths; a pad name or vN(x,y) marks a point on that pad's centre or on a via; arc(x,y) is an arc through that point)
+3V3: length 36
  TOP w0.254: C30.2 30.62,81.67 U8.8 ; C14.2 47,142.86 U1.1 ; U19.8 v1(46.65,25.49)
  TOP w0.356: C52.2 44.35,58.64 U13.22 ; U13.26 v1(40.61,61.24)
  TOP w0.508: 61.85,46.91 61.85,47.5 ; 61.85,47.5 61.85,48.08 ; 61.85,47.5 62.47,47.5 ; R1.2 v1(53.47,160.53) ; C71.1 63.25,44.69 ; C71.1 64.06,43.94 ; C71.1 62.43,43.94 ; v1(43.46,50.55) R77.2 U15.8 ; R88.1 v1(58.93,48.39) ; LD1.1 v1(19.94,3.05) ; LD2.1 v1(18.16,3.05) ; C30.2 v1(30.48,80.64) ; LD8.1 v1(16,50.04) ; C14.2 v1(45.72,142.88) ; 61.68,44.11 U16.4 61.27,44.64 ; R99.2 v1(45.47,26.04) ; C52.2 v1(44.93,57.18) ; 61.85,45.39 61.85,45.97 ; 61.85,45.97 61.85,46.56 ; 61.85,45.97 62.47,45.97 ; LD4.1 v1(14.61,3.05) ; LD3.1 v1(16.38,3.05)
  TOP w0.762: SB47.1 63.88,38.99 65.02,40.13 ; 65.66,38.61 65.66,40.01
  vias: v1(63.12,47.62) v1(63.12,46.86) v1(63.12,45.97) v1(63.88,47.62) v1(63.88,46.86) v1(63.88,45.97)
+3V3_PG: length 32.6
  TOP w0.381: U16.3 61.27,39.81 R91.1
  TOP w0.508: R80.2 v1(56.13,49.4) ; R91.1 v1(61.21,38.48) ; R115.2 v1(56.13,25.78)
  BOTTOM w0.508: v1(56.13,25.78) 56.77,26.42 56.77,33.91 61.21,38.35 v1(61.21,38.48) 61.21,44.32 v1(56.13,49.4)
+3V3_SD: length 66.3
  TOP w0.203: U6.15 v1(94.38,102.76)
  TOP w0.254: C41.2 97.14,67.93 U11.8 ; U10.8 87.77,67.93 C42.2
  TOP w0.508: C95.1 64.06,31.75 ; C95.1 62.43,31.75 ; C95.1 63.25,32.5 ; 96.52,34.62 CN14.9 ; CN14.9 95.58,35.56 ; CN14.9 97.46,35.56 ; 61.68,31.92 U21.4 61.27,32.45 ; R100.1 85.47,25.02 84.96,25.53 84.96,27.69 84.33,28.32 84.33,30.86 ; 61.85,35.31 61.85,36.7 61.34,37.21 59.56,37.21 58.93,36.58 R116.1 ; 61.85,35.31 62.47,35.31 ; 61.85,35.31 61.85,34.72 ; 99.06,34.62 CN14.10 ; CN14.10 98.12,35.56 ; CN14.10 101.75,35.56 TP13.1 ; SB15.2 v1(95.5,98.04) ; C41.2 v1(97.16,68.96) 96.9,69.22 89.03,69.22 87.88,68.07 C42.2 ; 61.85,33.2 61.85,33.78 ; 61.85,33.78 62.47,33.78 ; 61.85,33.78 61.85,34.37 ; v1(97.16,62.61) 92.96,62.61 v1(92.84,62.48) 92.2,61.85 R60.2 ; v1(94.11,109.6) 94.87,109.6 95.25,109.98 R34.2 ; CN8.4 v1(100.64,104.09) ; R75.2 v1(91.31,53.59)
  TOP w0.762: SB47.2 63.88,36.07 ; SB46.2 65.66,36.07
  BOTTOM w0.508: v1(91.31,53.59) 91.31,55.5 92.33,56.52 92.33,61.98 v1(92.84,62.48)
+3V3_SD_PG: length 2.6
  TOP w0.381: R114.1 61.27,28.01 U21.3
+3V3_ST_LINK: length 107.8
  TOP w0.254: C20.2 56.01,133.99 56.09,133.9 U2.36 ; U2.24 59.73,141.69 59.44,141.99 59.44,143.26 C13.2 ; U2.9 67.67,137.9 68.33,138.56 68.33,138.81 C15.2 ; v1(67.94,133.6) 67.94,133.65 67.69,133.9 U2.1 ; C21.2 65.23,130 U2.48
  TOP w0.508: C22.2 C23.1 45.41,123.51 U4.5 ; C22.2 43.48,123.57 ; C22.2 44.07,122.95 ; C20.2 v1(54.86,133.99) ; R17.2 v1(71.75,138.3) ; C13.2 v1(59.69,144.78) ; C15.2 v1(68.45,139.83) ; U4.5 45.9,121.34 ; U4.5 44.91,121.34 ; C21.2 v1(64.26,129.92)
  TOP w0.762: T1.3 9.44,128.1 10.29,127.25 28.07,127.25 v1(30.48,124.84) 32.51,122.81 32.51,118.62 33.78,117.35 37.72,117.35 41.78,121.41 42.55,121.41 ; R37.2 v1(11.81,105.92)
  BOTTOM w0.762: JP5.1 8.51,105.92 v1(11.81,105.92) 18.59,112.7 27.36,112.7 30.48,115.82 v1(30.48,124.84)
  vias: v1(42.16,123.57) v1(42.16,122.81) v1(42.93,123.57) v1(42.93,122.81)
+5V: length 40.4
  TOP w0.508: 11.76,59.31 TP10.1 ; TP10.1 12.7,58.37 ; TP10.1 12.7,60.25 ; TP10.1 13.64,59.31 ; 57.02,43.26 C72.1 ; C72.1 57.02,44.88 ; C72.1 56.08,44.07 ; C72.1 57.96,44.07 ; R96.1 v1(85.09,29.59) ; 9.58,55.5 JP17.1 ; JP17.1 10.41,54.66 ; JP17.1 11.25,55.5 ; JP17.1 10.41,56.34 ; R79.1 v1(64.9,50.55) ; 7.04,55.5 JP17.3 ; JP17.3 8.71,55.5 ; JP17.3 7.87,54.66 ; JP17.3 7.87,56.34 ; JP17.5 6.17,55.5 ; JP17.5 4.5,55.5 ; JP17.5 5.33,54.66 ; JP17.5 5.33,56.34 ; 12.64,56.39 R71.2 ; R71.2 13.21,55.8 ; R71.2 13.21,56.97 ; JP17.7 2.79,56.34 ; JP17.7 2.79,54.66 ; JP17.7 3.63,55.5 ; JP17.7 1.96,55.5 ; 57.15,55.5 58.09,55.5 ; 57.15,55.5 56.21,55.5 ; 57.15,55.5 57.15,56.31 ; 59.38,56.07 U14.6 58.97,55.54 ; R91.2 v1(58.8,39.75) ; D1.1 v1(68.6,126.35) ; 59.38,44.64 U16.6 58.97,44.11 ; R114.2 v1(63.88,27.81)
  BOTTOM w0.508: v1(58.67,32.26) 61.59,32.26 63.88,29.97 v1(63.88,27.81)
  vias: v1(54.99,44.7) v1(54.99,43.69) v1(54.99,36.32) v1(54.99,35.56) v1(55.63,56.13) v1(55.63,55.37) v1(55.75,44.55) v1(55.75,43.69) v1(55.75,36.32) v1(55.75,35.56)
D5V: length 159
  TOP w1.016: CN5.16 80.39,124.21 78.36,122.17 56.01,122.17 45.34,111.51 41.9,111.51 41.04,112.37 D3.1 40.79,113.67 35.56,113.67 25.53,103.63 25.53,85.14 24.46,84.07 ; 24.46,84.07 CN9.20 ; 24.46,84.07 24.38,84 24.38,81.15 23.24,80.01 15.67,80.01 v1(15.38,79.72) 15.37,79.71 v1(15.37,78.61)
  BOTTOM w1.016: v1(15.38,79.72) 15.37,79.71 v1(15.37,78.61) 15.37,63.27 15.9,62.74 15.9,51.92 13.41,49.43 9.88,49.43 7.87,51.44 JP17.4
GND: length 534.3
  TOP w0.229: U7.9 55.49,87.05 v1(55.55,87)
  TOP w0.254: U2.47 64.73,131.28 v1(64.39,130.94) ; U2.35 v1(59.56,134.4) ; U1.5 v1(50.68,141.36) ; v1(69.47,38.4) U17.5 ; U8.4 35.93,83.17 v1(36.45,83.69) ; U11.3 93.34,66.93 v1(93.6,66.67) 93.36,66.43 U11.4 ; U10.6 v1(84.96,66.93) ; U10.4 83.45,66.43 v1(83.82,66.8) 83.69,66.93 U10.3 ; U2.8 v1(65.41,137.4) ; D9.2 v1(64.39,15.27) ; U1.4 v1(49.53,141.36) ; U2.23 v1(60.23,142.37) ; U19.4 v1(40.51,23.54) ; U9.2 v1(104.39,77.47)
  TOP w0.305: U6.17 v1(96.14,101.73)
  TOP w0.356: U13.23 v1(40.61,59.29) ; U13.25 v1(43.78,60.59)
  TOP w0.381: CN6.5 5.11,134.21 v1(5.33,133.99)
  TOP w0.508: 110.55,75.39 CN12.10 ; CN12.10 111.49,76.33 ; CN12.10 109.61,76.33 ; CN12.10 110.55,77.27 ; 99.49,16.13 C91.1 ; C91.1 v1(101.09,16.13) ; C91.1 100.08,16.75 ; R26.1 v1(41.15,127.89) ; R26.1 41.15,126.16 ; R26.1 41.72,126.75 ; C93.2 60.71,27.56 v1(60.33,27.94) U21.2 ; C70.2 22.23,44.76 ; C70.2 19.51,43.05 ; C70.2 22.23,41.35 ; C70.2 24.94,43.05 ; 109.61,63.63 110.55,63.63 ; 110.55,63.63 111.49,63.63 ; 110.55,63.63 110.55,62.69 ; 110.55,63.63 110.55,64.57 ; 2.58,132.01 CN6.7 1.45,131.23 ; C88.1 v1(41.53,16.26) ; C88.1 42.55,16.88 ; C88.1 43.13,16.26 ; 9.27,137.85 C17.1 ; C17.1 9.89,138.43 ; C17.1 v1(9.27,139.57) ; 23.75,8.26 24.51,8.26 ; 23.75,8.26 23.75,7.49 ; 23.75,8.26 23.75,9.02 ; 23.75,8.26 22.99,8.26 ; R107.1 v1(43.05,20.57) ; R107.1 44.07,19.99 ; R107.1 44.07,21.16 ; C23.2 46.05,125.09 ; C23.2 v1(45.47,126.24) ; C23.2 44.88,125.09 ; v1(82.95,59.03) 83.06,59.03 83.54,58.55 C50.1 ; 76.71,9.41 B3.7 ; B3.7 v1(78.49,11.19) ; B3.7 77.95,9.68 ; 110.55,70.31 CN12.14 ; CN12.14 110.55,72.19 ; CN12.14 111.49,71.25 ; C14.1 v1(45.85,141.35) ; C16.1 70.74,141.97 ; C16.1 71.32,141.35 ; C16.1 70.15,141.35 ; C16.1 v1(71.63,142.24) ; C86.1 v1(81.66,23.7) ; R98.2 47.96,27.05 ; R98.2 v1(46.35,27.05) ; R98.2 47.37,26.48 ; C29.1 v1(28.96,84.2) ; C74.1 v1(73.28,37.97) ; B2.1 59.13,6.21 ; B2.1 60.07,5.52 ; B2.1 59.13,4.84 ; B2.1 v1(57.34,5.52) ; 110.55,67.77 CN12.16 ; CN12.16 109.61,68.71 ; CN12.16 111.49,68.71 ; CN12.16 110.55,69.65 ; 56.08,29.21 C92.2 ; C92.2 57.96,29.21 ; C92.2 57.02,30.02 ; C92.2 57.02,28.4 ; 57.02,40.46 C72.2 ; C72.2 56.08,41.27 ; C72.2 57.02,42.09 ; C72.2 57.96,41.27 ; CN11.10 8.89,67.41 ; CN11.10 7.57,64.95 ; CN11.10 10.21,64.95 ; CN11.10 8.89,62.48 ; 88.14,25.83 L4.1 ; L4.1 87.52,26.42 ; L4.1 v1(88.14,27.56) ; L4.1 88.76,26.42 ; 63.25,29.22 C95.2 ; C95.2 62.43,29.97 ; C95.2 64.06,29.97 ; C95.2 63.25,30.72 ; 57.15,51.89 C57.2 ; C57.2 58.09,52.7 ; C57.2 56.21,52.7 ; C57.2 57.15,53.52 ; C41.1 v1(98.68,68.96) ; 70.15,144.53 R15.1 ; R15.1 71.32,144.53 ; R15.1 v1(70.74,145.67) ; CN10.10 90.81,97.61 ; CN10.10 89.97,96.77 ; CN10.10 91.64,96.77 ; CN10.10 90.81,95.94 ; 97.03,15.54 R108.2 ; R108.2 v1(97.03,17.14) ; R108.2 96.46,16.13 ; 110.55,72.85 110.55,73.79 ; 110.55,73.79 111.49,73.79 ; 110.55,73.79 110.55,74.73 ; 109.61,66.17 CN12.18 ; CN12.18 110.55,67.11 ; CN12.18 111.49,66.17 ; CN12.18 110.55,65.23 ; 101.28,73.66 R52.1 ; R52.1 101.85,73.08 ; R52.1 v1(101.85,74.8) ; C24.1 47.96,125.09 ; C24.1 46.79,125.09 ; C24.1 v1(47.37,126.11) ; 49.53,165.02 CN1.32 49.53,163.14 ; C15.1 v1(68.33,141.35) ; R55.1 102.23,66.75 ; R55.1 102.23,65.58 ; R55.1 v1(101.22,66.17) ; TP1.1 37.39,167 ; TP1.1 36.45,166.06 ; TP1.1 35.51,167 ; TP1.1 36.45,167.95 ; CN17.2 107.49,14.86 ; CN17.2 106.55,15.8 ; CN17.2 106.55,13.92 ; CN17.2 105.61,14.86 ; CN10.17 89.1,86.61 ; CN10.17 87.43,86.61 ; CN10.17 88.27,87.45 ; CN10.17 88.27,85.78 ; R19.2 8.89,133.81 ; R19.2 8.89,132.64 ; R19.2 v1(9.78,133.22) ; U15.5 R85.2 v1(43.46,48.54) ; SB6.1 v1(73.66,141.35) ; 67.19,5.52 B2.4 ; B2.4 v1(69.53,5.52) ; B2.4 68.13,4.84 ; B2.4 68.13,6.21 ; B1.4 v1(49.72,5.52) ; B1.4 51.62,4.84 ; B1.4 51.62,6.21 ; B1.4 52.56,5.52 ; 26.29,4.95 RV2.2 ; RV2.2 25.53,5.71 ; RV2.2 27.05,5.71 ; RV2.2 26.29,6.48 ; R69.2 v1(69.72,55.88) ; 1.45,135.58 CN6.10 ; CN6.10 v1(2.94,136.51) ; CN6.10 1.45,137.44 ; CN9.17 19.68,87.45 ; CN9.17 19.68,85.78 ; CN9.17 18.85,86.61 ; 109.61,78.87 110.55,78.87 ; 110.55,78.87 110.55,77.93 ; 110.55,78.87 111.49,78.87 ; 110.55,78.87 110.55,79.81 ; 99.06,32.08 CN14.12 ; CN14.12 98.12,33.02 ; CN14.12 100,33.02 ; TP12.1 35.43,7.04 ; TP12.1 35.43,5.16 ; TP12.1 36.37,6.1 ; TP12.1 34.49,6.1 ; CN6.9 5.08,133.01 ; CN6.9 3.22,133.01 ; CN6.9 4.15,132.08 ; CN13.3 v1(86.11,75.44) ; 104.9,35.62 R92.1 ; R92.1 v1(103.76,36.2) ; R92.1 105.49,36.2 ; 81.87,4.25 B3.8 ; B3.8 83.38,5.76 ; B3.8 v1(83.62,4.01) ; C12.1 v1(54.61,145.8) ; C5.1 v1(56.26,160.53) ; LD7.2 v1(13.21,53.34) ; C30.1 v1(28.96,80.64) ; CN8.9 v1(100.75,109.64) ; v1(43.78,60.59) 43.89,60.48 C48.2 ; CN11.11 10.21,89.99 ; CN11.11 7.57,89.99 ; CN11.11 8.89,92.46 ; CN11.11 8.89,87.53 ; BT1.2 36.93,38.1 ; BT1.2 v1(34.72,40.59) ; BT1.2 v1(30.86,38.1) ; BT1.2 34.72,36.84 ; 42.62,4.84 B1.1 ; B1.1 42.62,6.21 ; B1.1 v1(44.51,5.52) ; B1.1 41.68,5.52 ; 63.25,41.41 C71.2 ; C71.2 62.43,42.16 ; C71.2 64.06,42.16 ; C71.2 63.25,42.91 ; C4.1 v1(52.07,156.72) ; C20.1 v1(54.86,132.46) ; 110.55,83.95 111.49,83.95 ; 110.55,83.95 110.55,83.01 ; 110.55,83.95 109.61,83.95 ; 110.55,83.95 110.55,84.89 ; D6.5 v1(94.36,40.01) ; C21.1 v1(65.15,127.51) ; R86.1 98.37,47.62 ; R86.1 97.79,48.2 ; R86.1 v1(96.65,47.62) ; R58.1 102.23,64.21 ; R58.1 102.23,63.04 ; R58.1 v1(101.09,63.63) ; 64.9,52.97 C56.2 ; C56.2 64.08,53.72 ; C56.2 65.71,53.72 ; CN4.5 37.16,152.15 ; CN4.5 35.48,152.15 ; CN4.5 36.32,151.31 ; R27.2 v1(63.37,123.95) ; CN12.6 110.55,82.35 ; CN12.6 110.55,80.47 ; CN12.6 109.61,81.41 ; CN12.6 111.49,81.41 ; R23.1 v1(63.37,127.51) ; CN13.9 v1(86.23,71.63) ; CN6.8 4.15,138.94 ; CN6.8 3.22,138.01 ; CN6.8 5.08,138.01 ; TP11.1 111.56,50.93 ; TP11.1 110.62,51.87 ; TP11.1 110.62,49.99 ; TP11.1 109.68,50.93 ; C69.2 v1(70.23,45.21) ; R87.2 v1(56.52,47.5) ; 109.17,45.91 CN15.3 ; CN15.3 110.35,44.49 ; CN15.3 111.53,45.91 ; CN15.3 v1(110.35,47.77) ; R81.1 v1(33.4,52.2) ; C1.1 v1(45.34,160.53) ; C13.1 v1(58.17,144.78) ; R25.1 v1(68.07,127.51) ; C42.1 v1(88.39,66.8) ; U16.2 U16.7 ; v1(73.03,76.83) C39.2 v1(71.5,75.44) ; C22.1 44.65,125.09 ; C22.1 v1(44.07,126.24) ; C22.1 43.48,125.09 ; C87.1 v1(84.71,23.7) ; v1(69.22,51.56) C59.2 v1(70.74,52.7) ; CN13.5 v1(86.11,74.17) ; 12.88,131.32 R20.1 ; R20.1 14.05,131.32 ; R20.1 v1(13.46,132.33) ; C35.2 v1(52.7,78.36) ; C62.2 60.71,51.18 v1(60.33,51.56) U14.2 ; v1(88.27,50.42) C58.2 v1(86.84,51.82) ; v1(60.33,36.2) C96.2 ; C90.1 v1(92.46,17.14) ; L2.5 1.6,40.79 ; L2.5 2.77,39.62 ; L2.5 1.6,38.46 ; C26.1 v1(45.47,114.68) ; v1(23.62,121.92) 24,121.54 U5.2 ; CN8.6 v1(100.75,106.29) ; R24.1 v1(66.67,127.51) ; v1(72.01,51.56) C60.2 v1(73.28,52.7) ; C19.2 v1(71.88,135.25) ; 67.61,14.73 R110.1 ; R110.1 v1(68.2,13.59) ; R110.1 68.78,14.73 ; 69.34,31.88 v1(68.33,31.88) ; R51.1 v1(97.43,73.41) ; v1(72.77,80.26) C31.2 v1(71.5,78.99) ; C34.2 v1(48.26,78.36) ; CN2.7 v1(13.21,148.96) ; CN2.7 11.57,148.27 ; CN2.7 11.57,149.65 ; 1.45,139.78 CN6.6 2.58,139.01 ; R78.1 v1(95,50.8) ; 61.85,79.38 v1(61.85,78.49) ; C54.2 v1(78.87,56.64) ; C27.1 v1(46.99,114.68) ; R8.1 v1(74.8,160.53) ; v1(80.26,50.42) C61.2 v1(81.53,51.56) ; C2.1 v1(42.55,156.72) ; C52.1 v1(46.46,57.18) ; D6.2 v1(88.9,40.01) ; 62.53,53.98 C55.2 ; C55.2 63.7,53.98 ; C55.2 63.12,53.35 ; R117.2 v1(57.53,36.2) ; C8.1 v1(67.44,160.53) ; C11.1 v1(45.34,156.72) ; U3.2 v1(8.38,135.76) ; 42.77,23.54 U19.4 41.83,23.18 ; 97.46,33.02 CN14.11 96.52,32.08 ; C64.2 v1(60.33,48.51) ; C84.1 v1(75.31,23.7) ; v1(28.96,119.89) 27.94,119.89 C28.2 27.94,120.65 v1(28.96,120.65) ; U12.2 v1(78.61,59.18) ; RV3.3 96.01,9.02 ; RV3.3 96.01,7.49 ; RV3.3 95.25,8.26 ; RV3.3 96.77,8.26 ; C6.1 v1(59.31,160.53) ; CN6.11 1.45,135.44 ; CN6.11 1.45,133.58 ; CN6.11 v1(2.92,134.51) ; D8.2 v1(76.45,15.49) ; v1(74.8,36.96) 74.8,37.59 C75.2 75.69,37.72 v1(75.69,36.96) ; C36.2 v1(57.28,78.49) ; R16.1 v1(62.99,144.53) ; C46.2 v1(77.72,62.87) ; U4.2 v1(46.35,120.04) ; SB14.2 v1(58.42,105.54) ; C3.1 v1(43.81,156.72) ; C43.1 v1(98.68,65.15) ; C44.2 v1(31.34,64.16) ; C40.1 v1(79.63,69.72) ; C9.1 v1(70.23,160.53) ; C10.1 v1(76.33,160.53) ; C85.1 v1(78.49,23.7) ; LD6.1 v1(1.11,108.17) ; C83.1 v1(72.14,23.7) ; C25.1 v1(21.97,123.06) ; C65.1 v1(68.33,48.13) ; C18.2 v1(71.88,136.78) ; C7.1 v1(64.26,160.53)
  BOTTOM w0.508: 25.53,5.71 RV2.2 ; RV2.2 27.05,5.71 ; RV2.2 26.29,6.48 ; RV2.2 26.29,4.95 ; CN12.16 110.55,69.65 ; CN12.16 109.61,68.71 ; CN12.16 110.55,67.77 ; CN12.16 111.49,68.71 ; TP11.1 110.62,51.87 ; TP11.1 110.62,49.99 ; TP11.1 111.56,50.93 ; TP11.1 109.68,50.93 ; 109.61,71.25 CN12.14 ; CN12.14 111.49,71.25 ; CN12.14 110.55,72.19 ; CN12.14 110.55,70.31 ; 55.37,127.58 CN7.2 ; CN7.2 56.31,128.52 ; CN7.2 55.37,129.46 ; CN7.2 54.43,128.52 ; 34.49,6.1 TP12.1 ; TP12.1 35.43,7.04 ; TP12.1 36.37,6.1 ; TP12.1 35.43,5.16 ; CN1.4 86.03,164.08 ; CN1.4 84.15,164.08 ; CN1.4 85.09,163.14 ; CN1.4 85.09,165.02 ; 74.93,163.14 CN1.12 ; CN1.12 75.87,164.08 ; CN1.12 74.93,165.02 ; CN1.12 73.99,164.08 ; CN6.8 4.15,138.94 ; CN6.8 5.08,138.01 ; CN6.8 4.15,137.08 ; CN6.8 3.22,138.01 ; CN12.10 110.55,77.27 ; CN12.10 109.61,76.33 ; CN12.10 110.55,75.39 ; CN12.10 111.49,76.33 ; 80.01,163.14 CN1.8 ; CN1.8 80.95,164.08 ; CN1.8 80.01,165.02 ; CN1.8 79.07,164.08 ; 109.61,63.63 110.55,63.63 ; 110.55,63.63 110.55,64.57 ; 110.55,63.63 110.55,62.69 ; 110.55,63.63 111.49,63.63 ; 96.52,32.08 CN14.11 ; CN14.11 95.58,33.02 ; CN14.11 96.52,33.96 ; CN14.11 97.46,33.02 ; CN1.30 53.01,164.08 ; CN1.30 52.07,163.14 ; CN1.30 52.07,165.02 ; C32.1 C33.2 55.75,87 v1(55.55,87) ; L2.5 2.77,39.62 ; L2.5 1.6,38.46 ; L2.5 1.6,40.79 ; CN1.10 78.41,164.08 ; CN1.10 77.47,165.02 ; CN1.10 77.47,163.14 ; CN1.10 76.53,164.08 ; CN11.5 10.29,73 ; CN11.5 9.09,71.93 ; CN11.5 11.48,71.93 ; CN11.5 10.29,70.87 ; 109.61,81.41 CN12.6 ; CN12.6 111.49,81.41 ; CN12.6 110.55,80.47 ; CN12.6 110.55,82.35 ; L2.4 6.6,40.79 ; L2.4 7.77,39.62 ; L2.4 5.44,39.62 ; L2.4 6.6,38.46 ; 109.61,66.17 CN12.18 ; CN12.18 111.49,66.17 ; CN12.18 110.55,67.11 ; CN12.18 110.55,65.23 ; CN1.22 63.17,164.08 ; CN1.22 62.23,165.02 ; CN1.22 62.23,163.14 ; 48.59,164.08 CN1.32 49.53,165.02 ; 7.57,89.99 CN11.11 ; CN11.11 10.21,89.99 ; CN11.11 8.89,87.53 ; CN11.11 8.89,92.46 ; CN1.20 65.71,164.08 ; CN1.20 63.83,164.08 ; CN1.20 64.77,165.02 ; CN1.20 64.77,163.14 ; CN17.2 106.55,15.8 ; CN17.2 107.49,14.86 ; CN17.2 106.55,13.92 ; CN17.2 105.61,14.86 ; CN1.16 69.85,165.02 ; CN1.16 69.85,163.14 ; CN1.16 68.91,164.08 ; 110.55,73.79 110.55,74.73 ; 110.55,73.79 109.61,73.79 ; 110.55,73.79 111.49,73.79 ; 110.55,73.79 110.55,72.85 ; CN1.18 67.31,165.02 ; CN1.18 67.31,163.14 ; CN1.18 68.25,164.08 ; CN1.18 66.37,164.08 ; CN1.6 82.55,165.02 ; CN1.6 82.55,163.14 ; CN1.6 81.61,164.08 ; CN1.6 83.49,164.08 ; RV3.3 96.77,8.26 ; RV3.3 95.25,8.26 ; RV3.3 96.01,9.02 ; RV3.3 96.01,7.49 ; 98.12,33.02 CN14.12 ; CN14.12 99.06,33.96 ; CN14.12 100,33.02 ; CN14.12 99.06,32.08 ; 110.55,78.87 111.49,78.87 ; 110.55,78.87 110.55,77.93 ; 110.55,78.87 109.61,78.87 ; 110.55,78.87 110.55,79.81 ; CN6.9 4.15,133.94 ; CN6.9 4.15,132.08 ; CN6.9 5.08,133.01 ; CN6.9 3.22,133.01 ; 7.57,64.95 CN11.10 ; CN11.10 10.21,64.95 ; CN11.10 8.89,67.41 ; CN11.10 8.89,62.48 ; 23.75,8.26 24.51,8.26 ; 23.75,8.26 23.75,9.02 ; 23.75,8.26 23.75,7.49 ; 23.75,8.26 22.99,8.26 ; 59.69,163.14 CN1.24 59.69,165.02 ; 87.63,163.14 CN1.2 ; CN1.2 86.69,164.08 ; CN1.2 87.63,165.02 ; CN1.2 88.57,164.08 ; 1.45,131.23 CN6.7 ; CN6.7 1.45,132.78 ; CN6.7 2.58,132.01 ; 7.94,42.12 L2.6 ; L2.6 10.27,42.12 ; L2.6 9.1,40.96 ; L2.6 9.1,43.29 ; 110.55,83.95 110.55,84.89 ; 110.55,83.95 110.55,83.01 ; 110.55,83.95 111.49,83.95 ; 110.55,83.95 109.61,83.95 ; CN6.6 1.45,139.78 ; CN6.6 1.45,138.23 ; CN6.6 2.58,139.01 ; C38.1 v1(53.72,90.55)
  vias: v1(0.89,19.05) v1(1.02,120.14) v1(1.02,33.53) v1(1.02,11.56) v1(1.14,163.83) v1(1.14,129.92) v1(1.14,124.97) v1(1.14,114.81) v1(1.14,110.24) v1(1.14,1.4) v1(1.27,159.13) v1(1.27,144.27) v1(1.4,171.32) v1(9.65,1.14) v1(11.56,171.7) v1(18.16,1.14) v1(18.92,149.48) v1(20.7,171.45) v1(21.21,46.61) v1(21.21,45.85) v1(22.1,46.61) v1(22.1,45.85) v1(25.02,148.84) v1(25.53,20.57) v1(27.3,20.57) v1(28.83,20.57) v1(32.05,143.31) v1(32.51,1.02) v1(32.77,171.7) v1(32.82,136.96) v1(40.51,1.14) v1(41.53,161.04) v1(41.91,171.7) v1(42.16,151.76) v1(48.51,161.8) v1(48.51,134.62) v1(50.67,132.59) v1(51.18,1.02) v1(51.31,128.14) v1(51.94,171.7) v1(55.24,37.59) v1(55.24,22.86) v1(55.63,53.21) v1(55.63,52.2) v1(55.63,41.53) v1(55.63,40.64) v1(55.63,29.59) v1(55.63,28.83) v1(57.15,1.14) v1(58.67,42.67) v1(58.67,41.91) v1(58.67,30.73) v1(58.67,29.97) v1(58.8,54.48) v1(58.8,53.59) v1(61.47,171.7) v1(61.96,54.36) v1(61.96,53.59) v1(61.98,42.67) v1(61.98,41.91) v1(61.98,30.61) v1(61.98,29.84) v1(64.26,52.58) v1(65.41,52.58) v1(65.66,23.5) v1(68.33,0.89) v1(72.39,150.24) v1(72.52,143.38) v1(74.17,171.83) v1(80.39,132.97) v1(80.39,125.98) v1(80.77,140.97) v1(81.92,171.83) v1(84.58,1.02) v1(85.09,133.1) v1(85.22,140.59) v1(85.34,149.86) v1(85.34,126.24) v1(90.68,1.02) v1(94.11,171.7) v1(103.12,102.62) v1(103.25,120.14) v1(103.25,114.3) v1(103.38,128.02) v1(103.38,32.13) v1(104.52,171.58) v1(106.81,0.89) v1(108.08,139.83) v1(108.2,149.22) v1(108.2,130.81) v1(112.27,107.19) v1(112.52,100.46) v1(112.9,76.33) v1(113.03,153.29) v1(113.03,144.65) v1(113.03,125.86) v1(113.03,118.36) v1(113.03,84.58) v1(113.03,69.72) v1(113.03,39.75) v1(113.03,25.02) v1(113.16,171.45) v1(113.16,160.66) v1(113.16,135.25) v1(113.16,112.39) v1(113.16,90.93) v1(113.16,61.98) v1(113.16,55.88) v1(113.16,32.89) v1(113.28,1.02) v1(113.41,49.02)
